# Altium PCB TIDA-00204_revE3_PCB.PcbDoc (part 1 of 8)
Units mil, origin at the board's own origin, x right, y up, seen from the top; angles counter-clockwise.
Board outline 4600 x 3740 mil, 8 copper layers (TopLayer - S1 (.GTL), MidLayer1 - S2 (.G1), MidLayer2 - S3 (.G2), MidLayer3 - S4 (.G3), MidLayer4 - S5 (.G4), MidLayer5 - S6 (.G5), MidLayer6 - S7 (.G6), BottomLayer - S8 (.GBL)), stack 58.938 mil thick; 536 components, 354 nets, 2015 pads, 1067 vias.
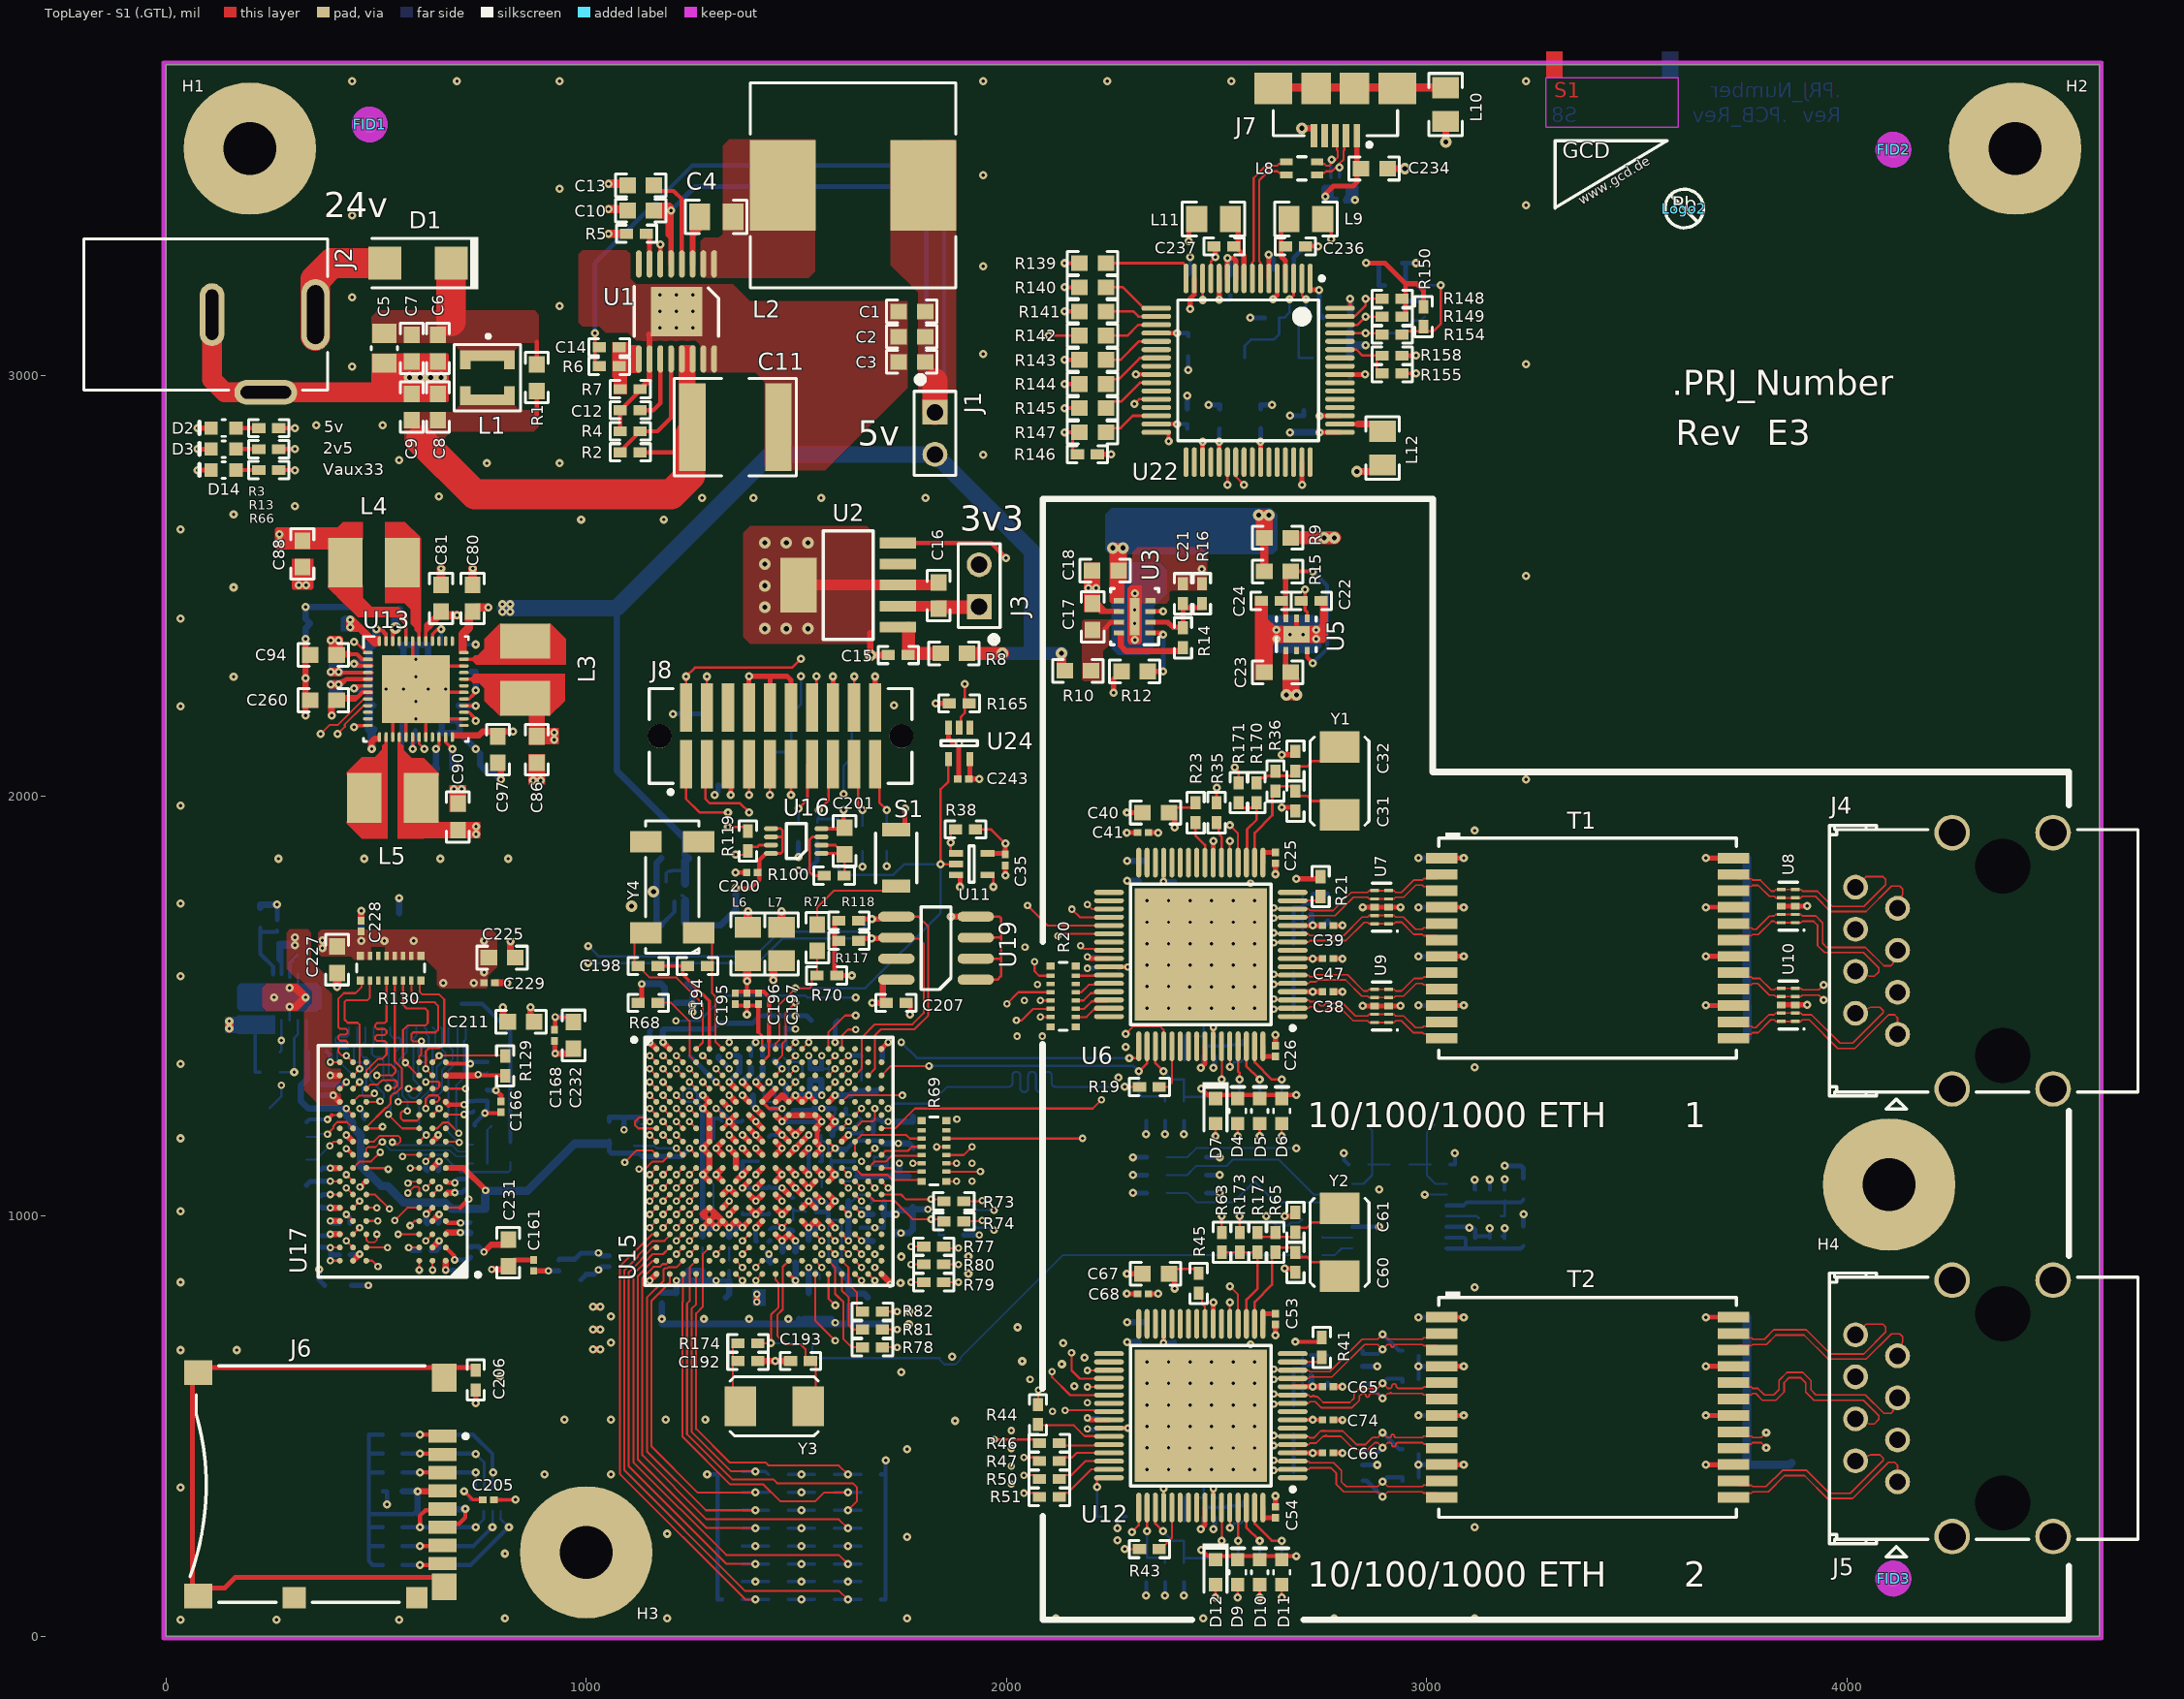
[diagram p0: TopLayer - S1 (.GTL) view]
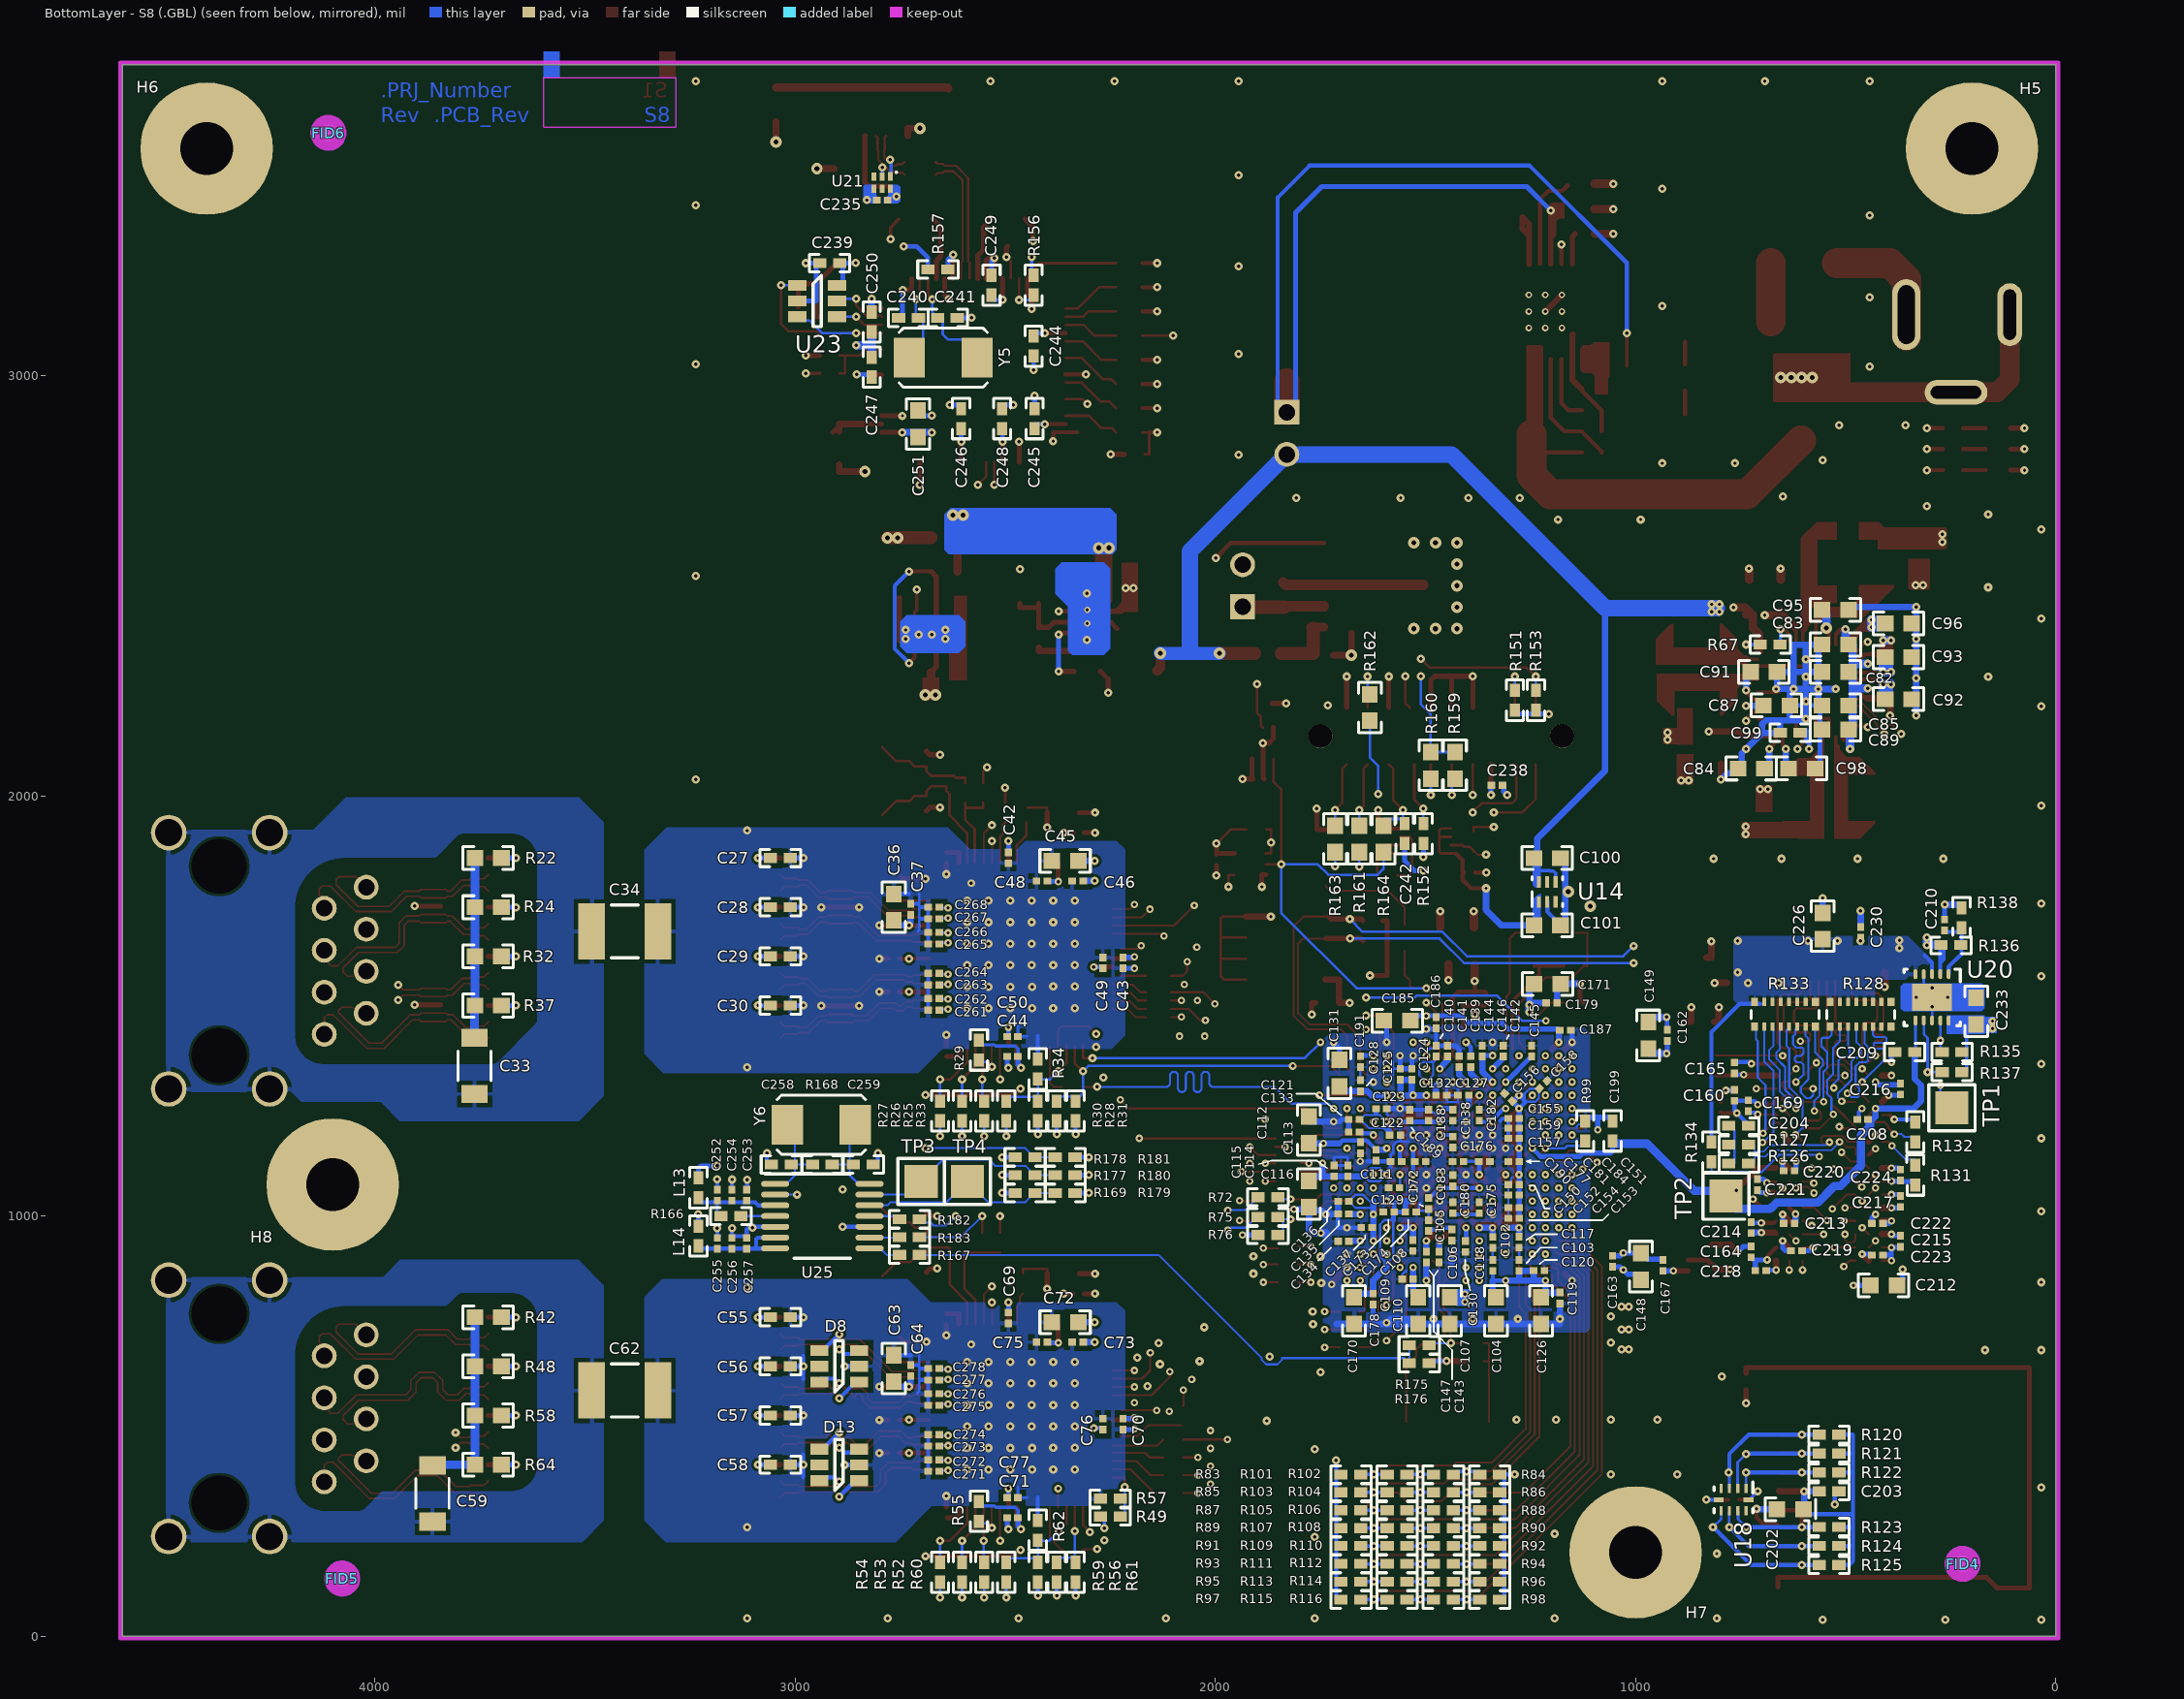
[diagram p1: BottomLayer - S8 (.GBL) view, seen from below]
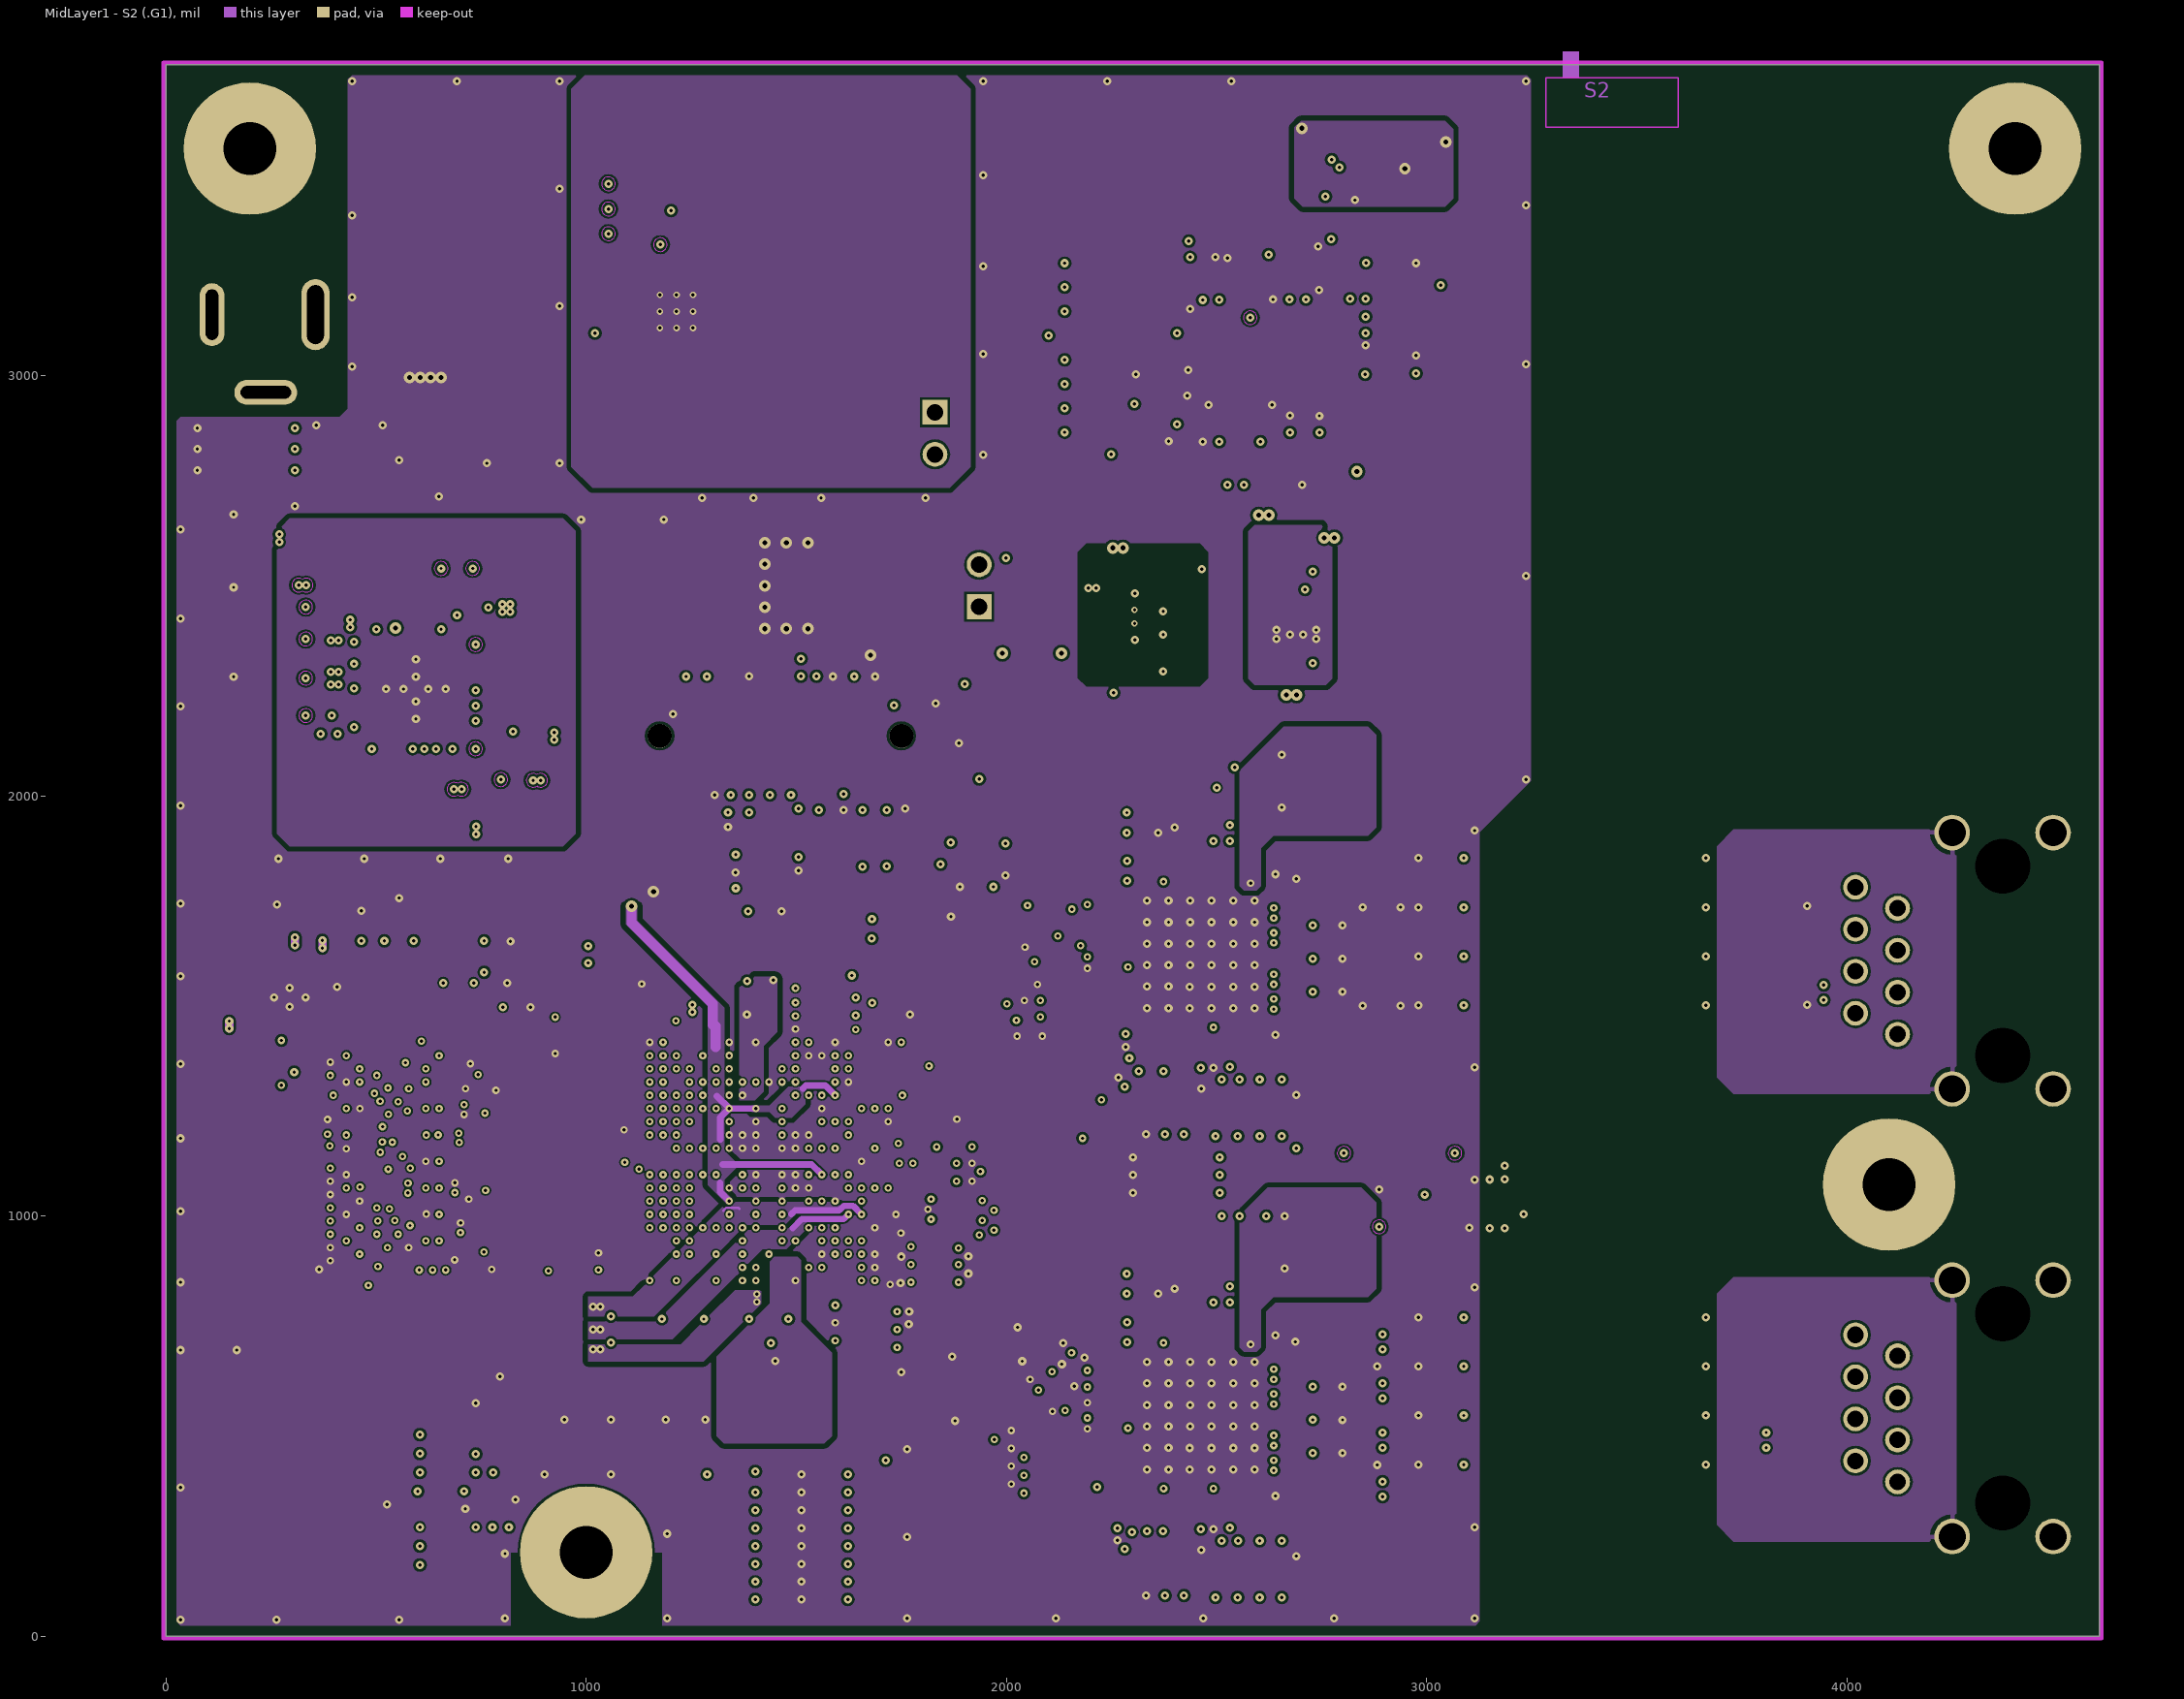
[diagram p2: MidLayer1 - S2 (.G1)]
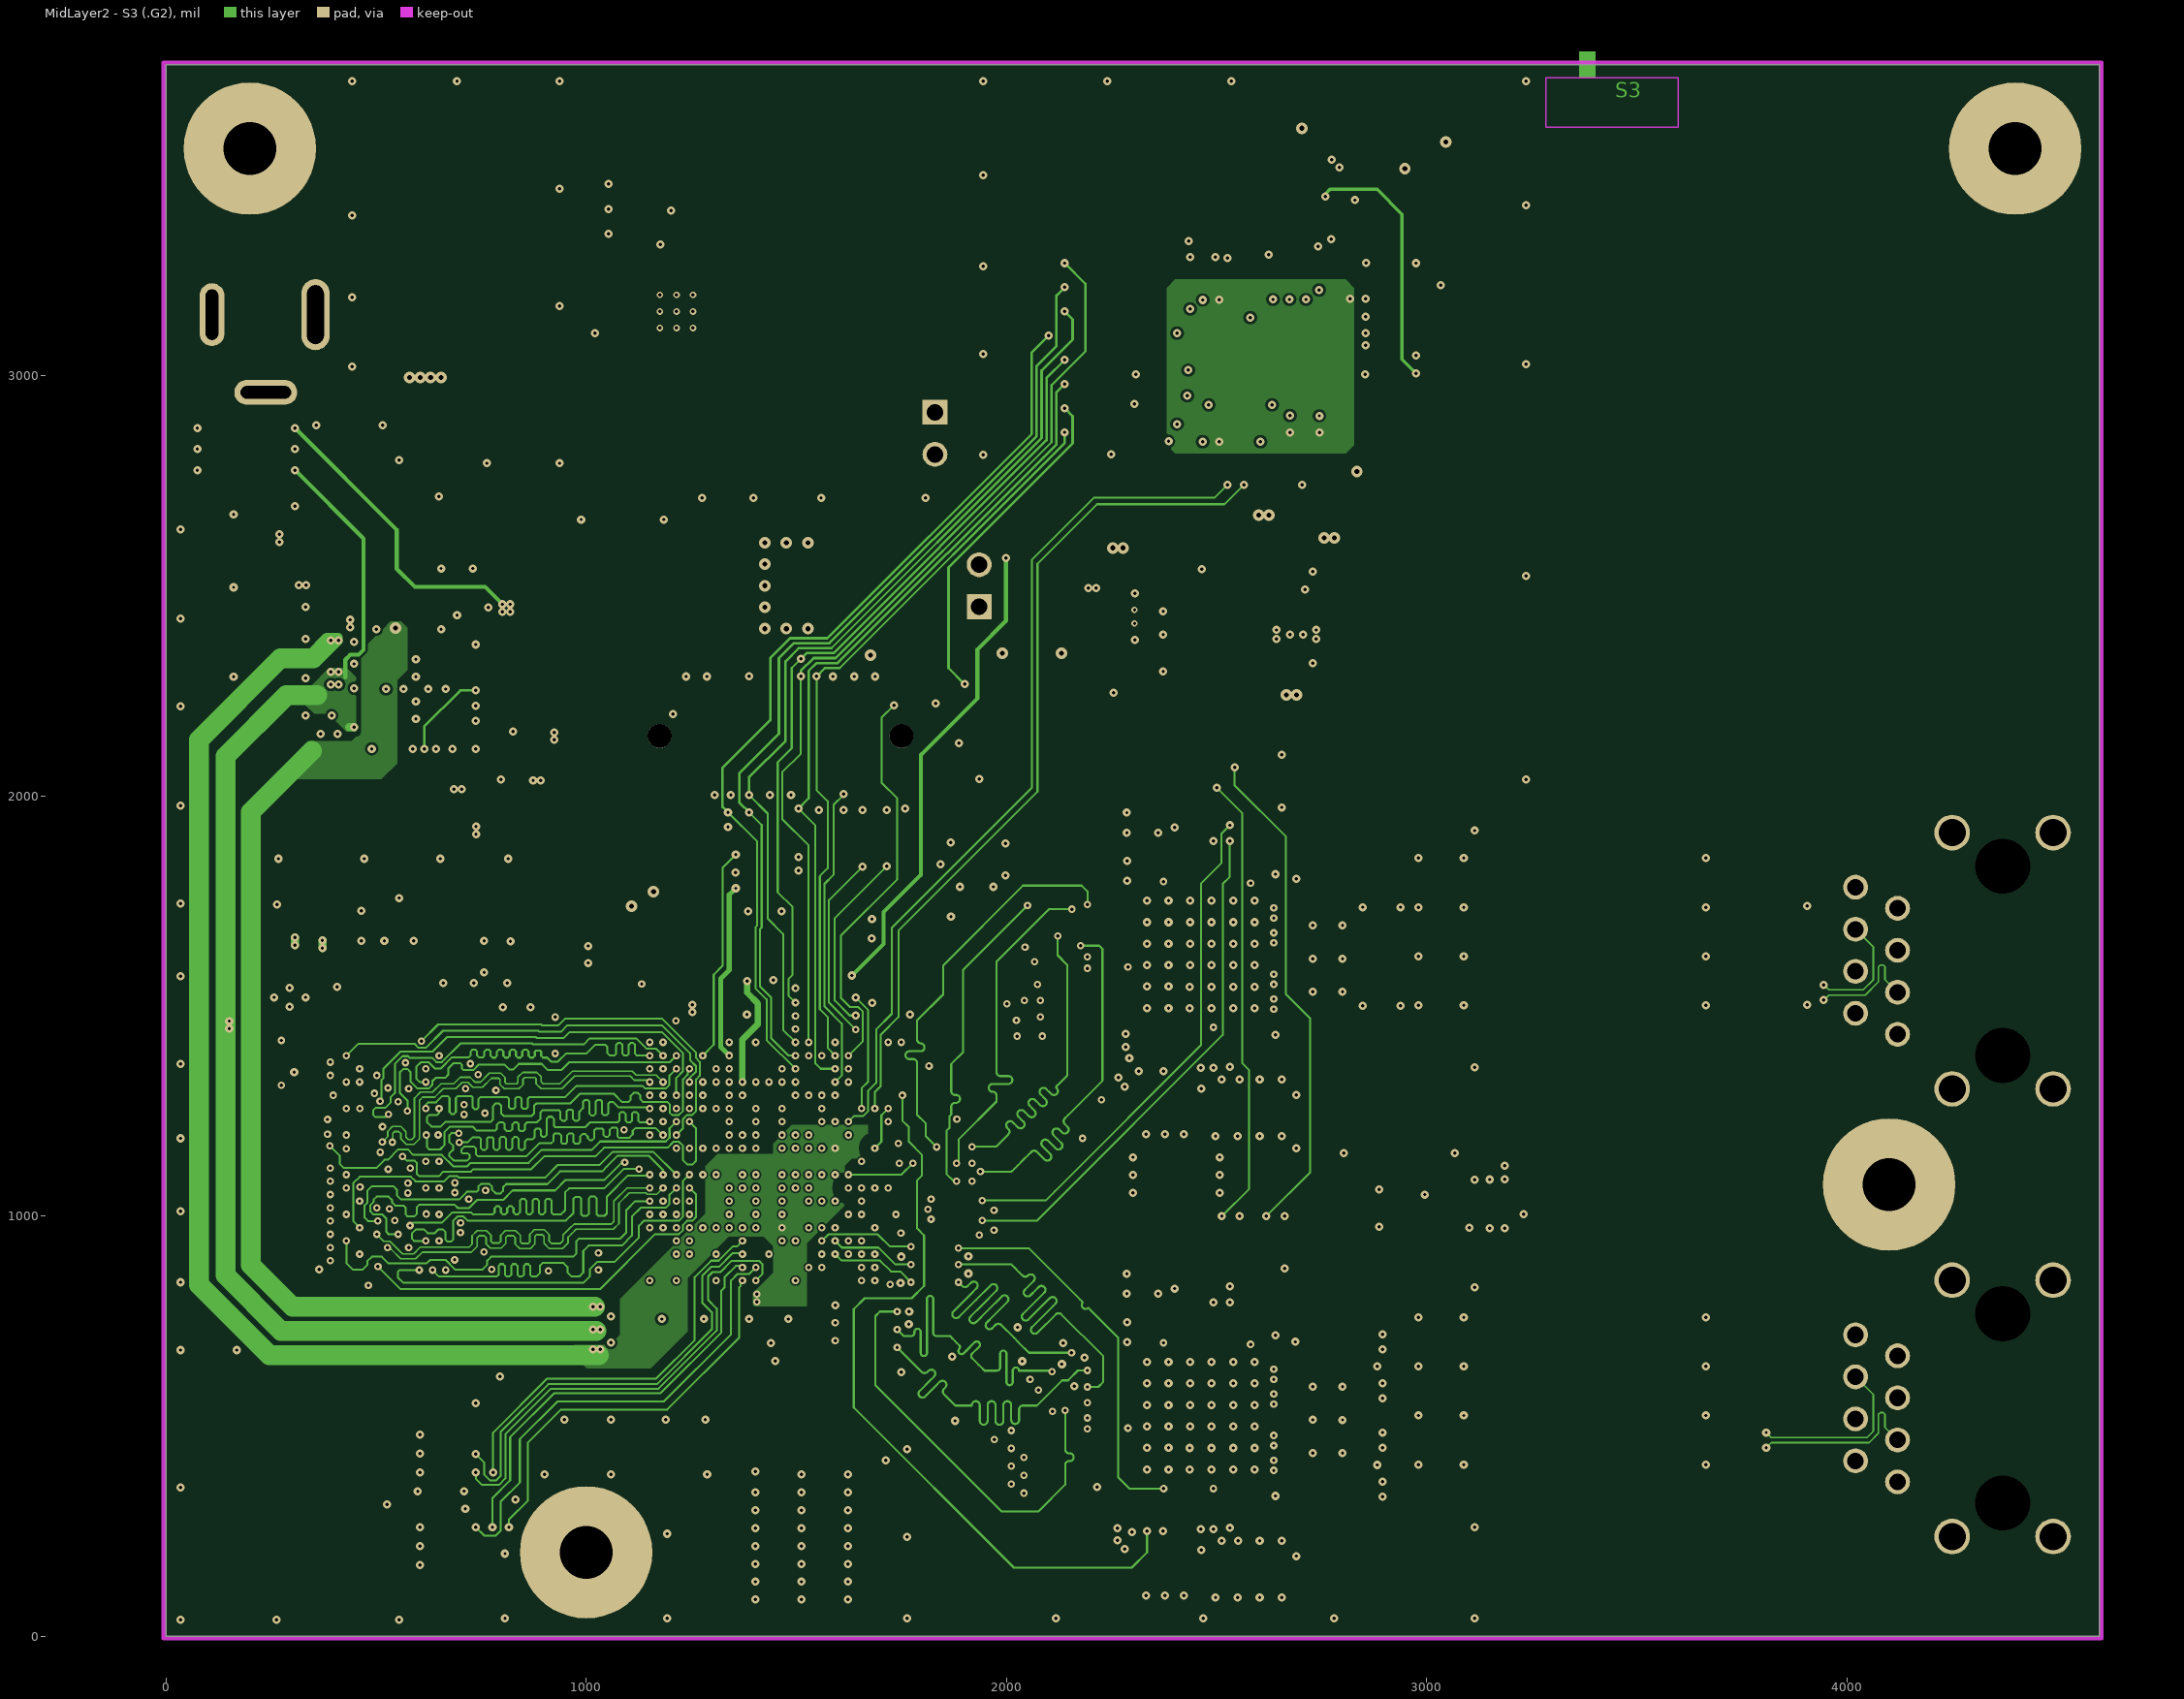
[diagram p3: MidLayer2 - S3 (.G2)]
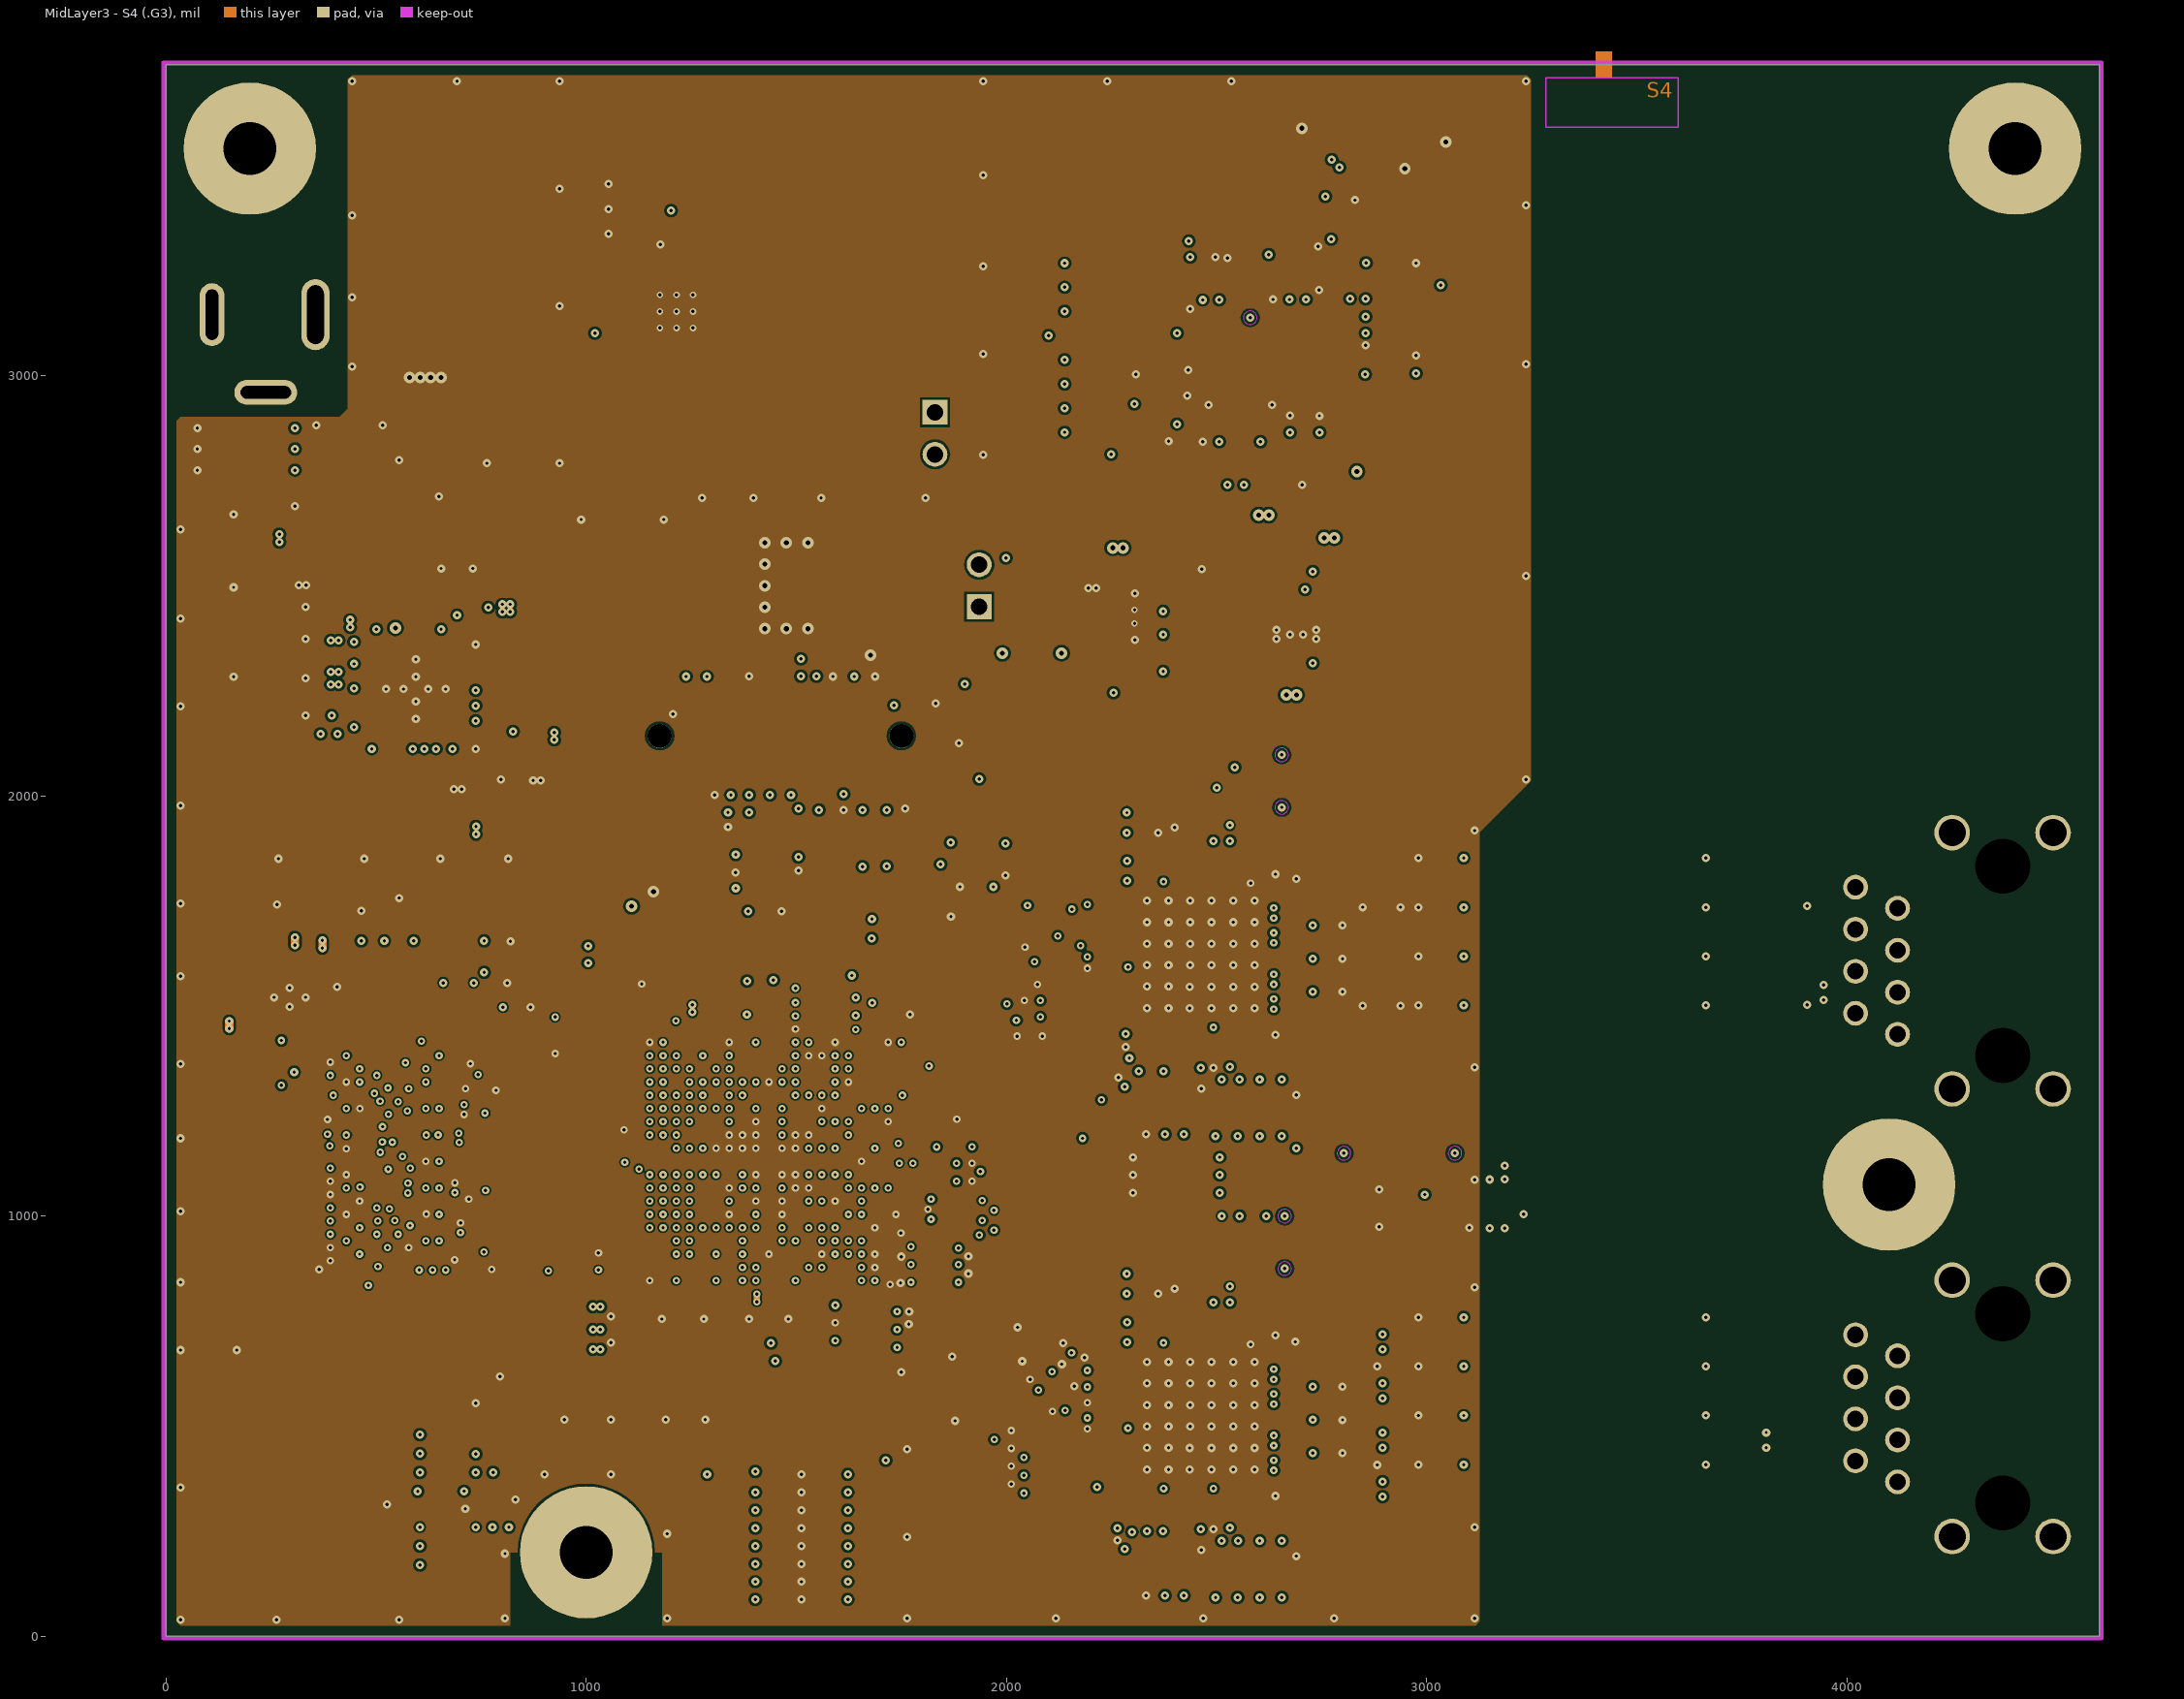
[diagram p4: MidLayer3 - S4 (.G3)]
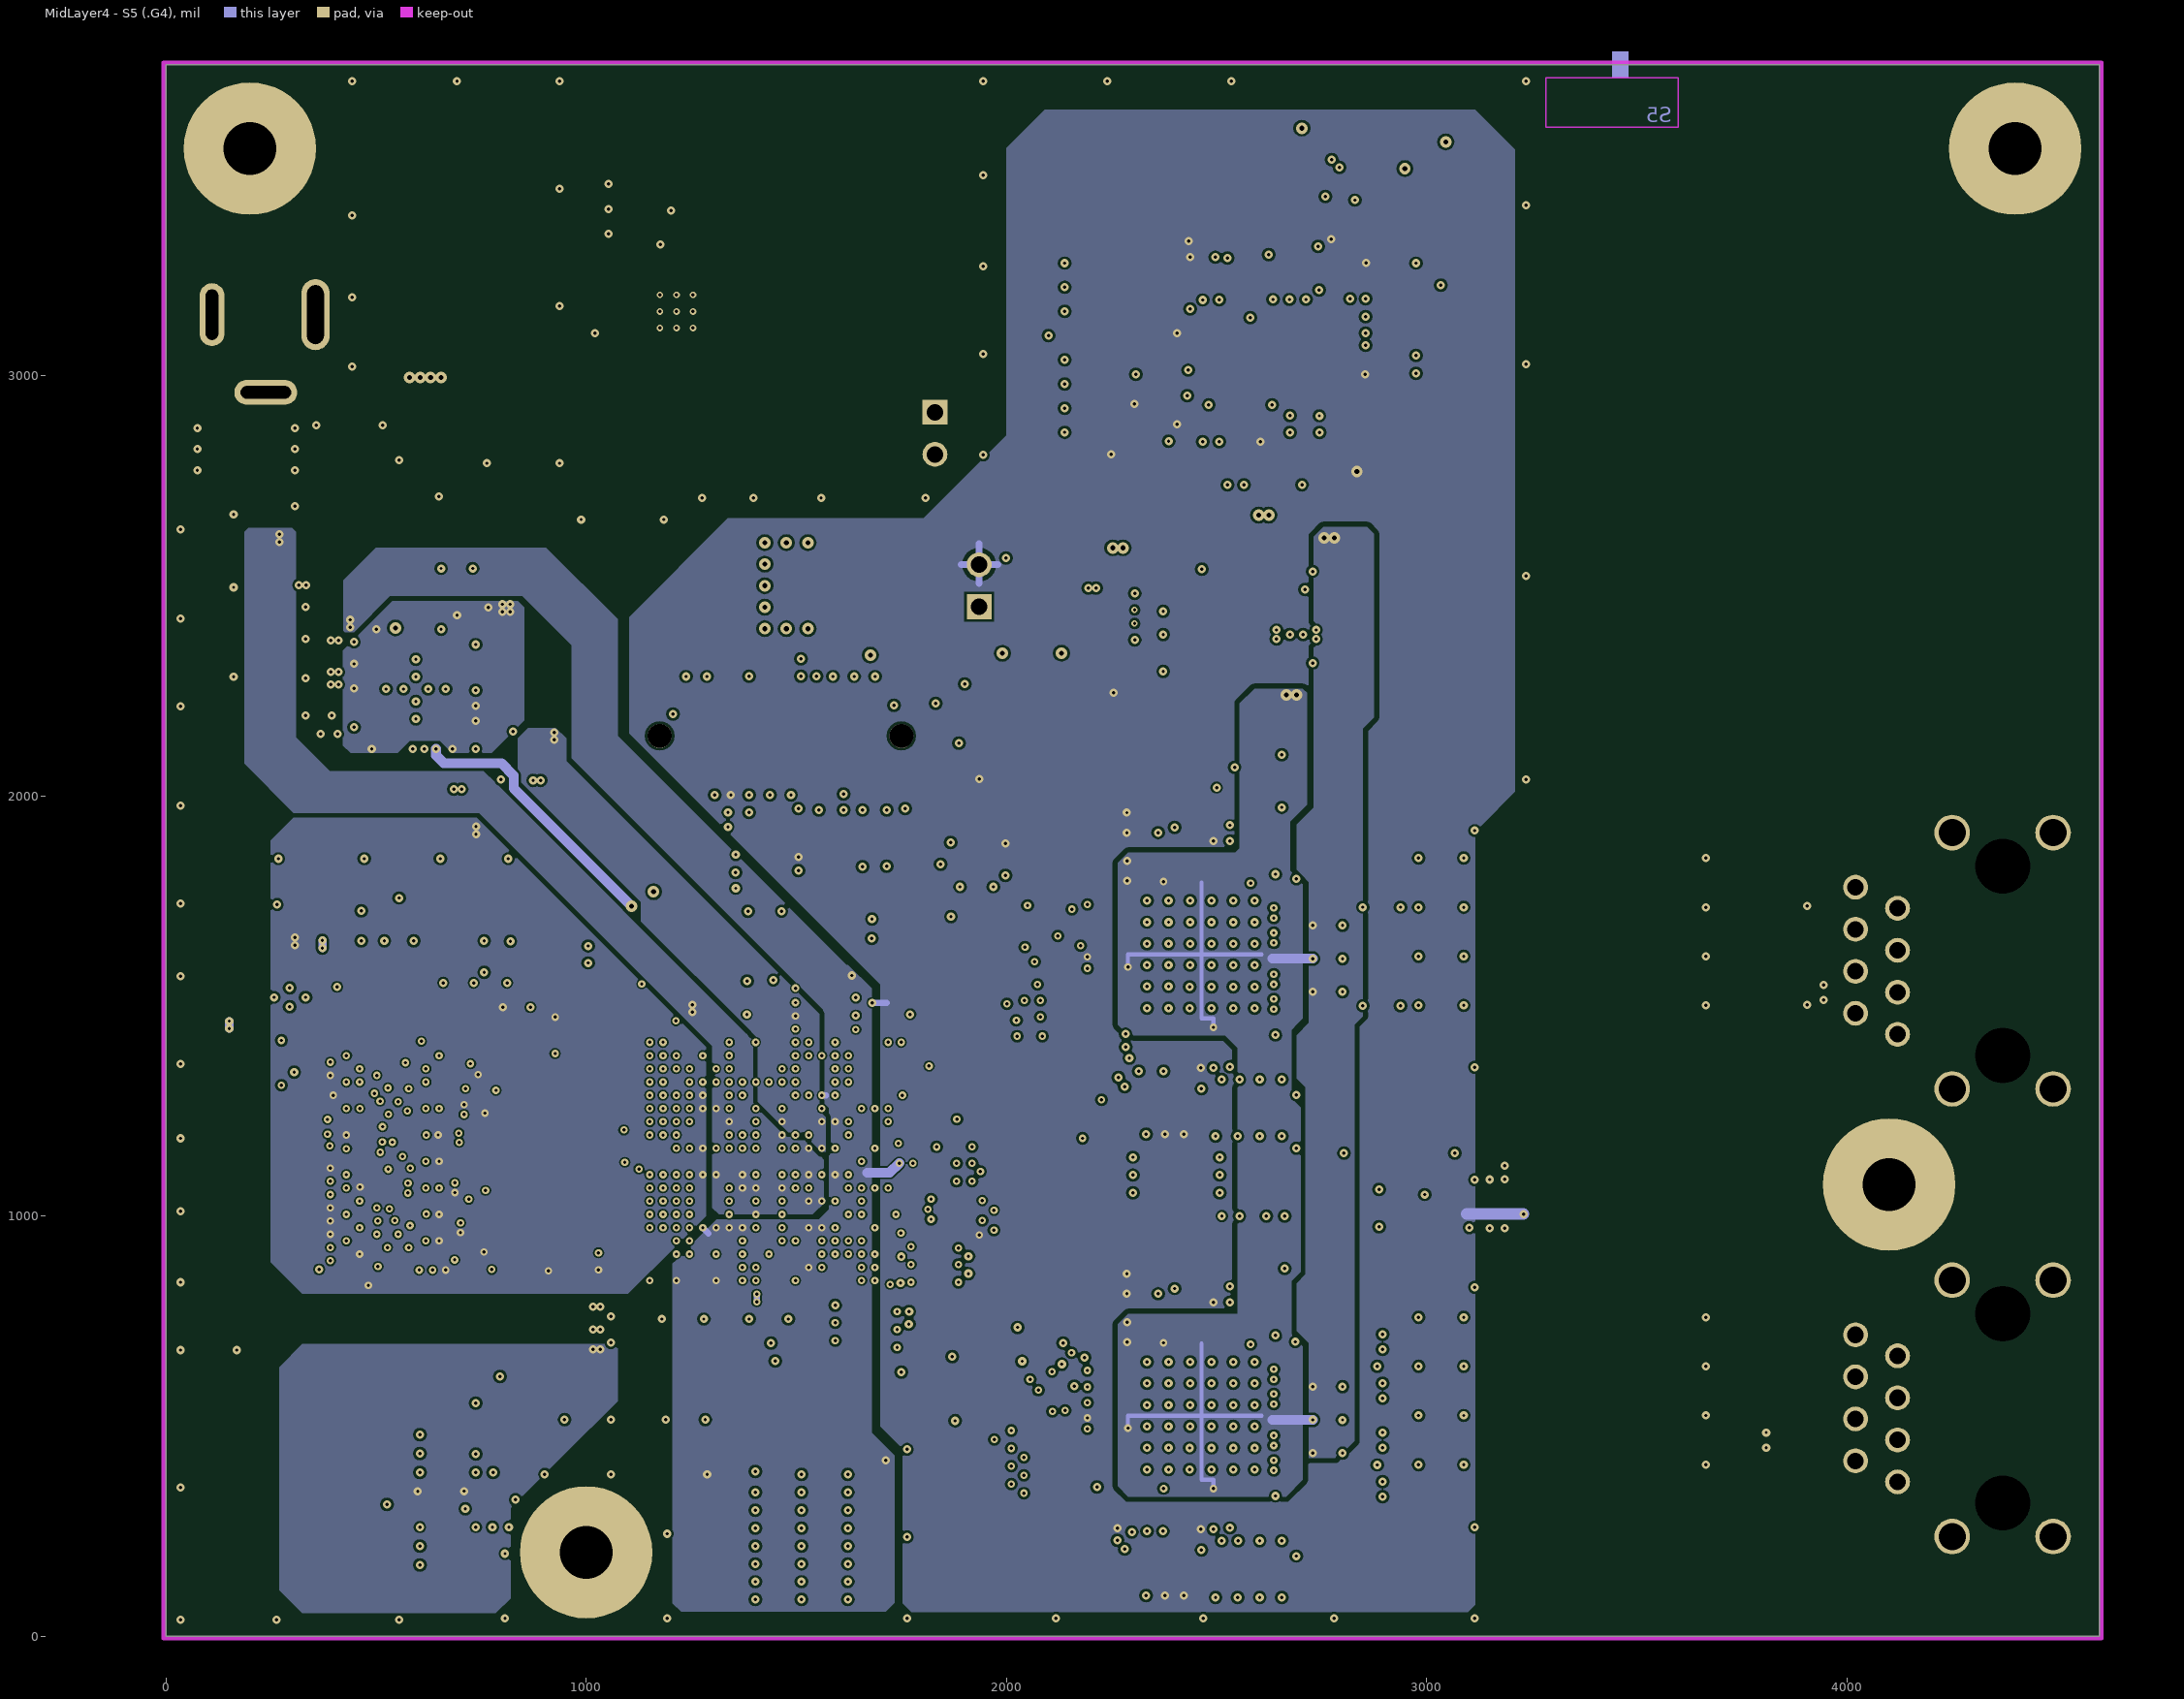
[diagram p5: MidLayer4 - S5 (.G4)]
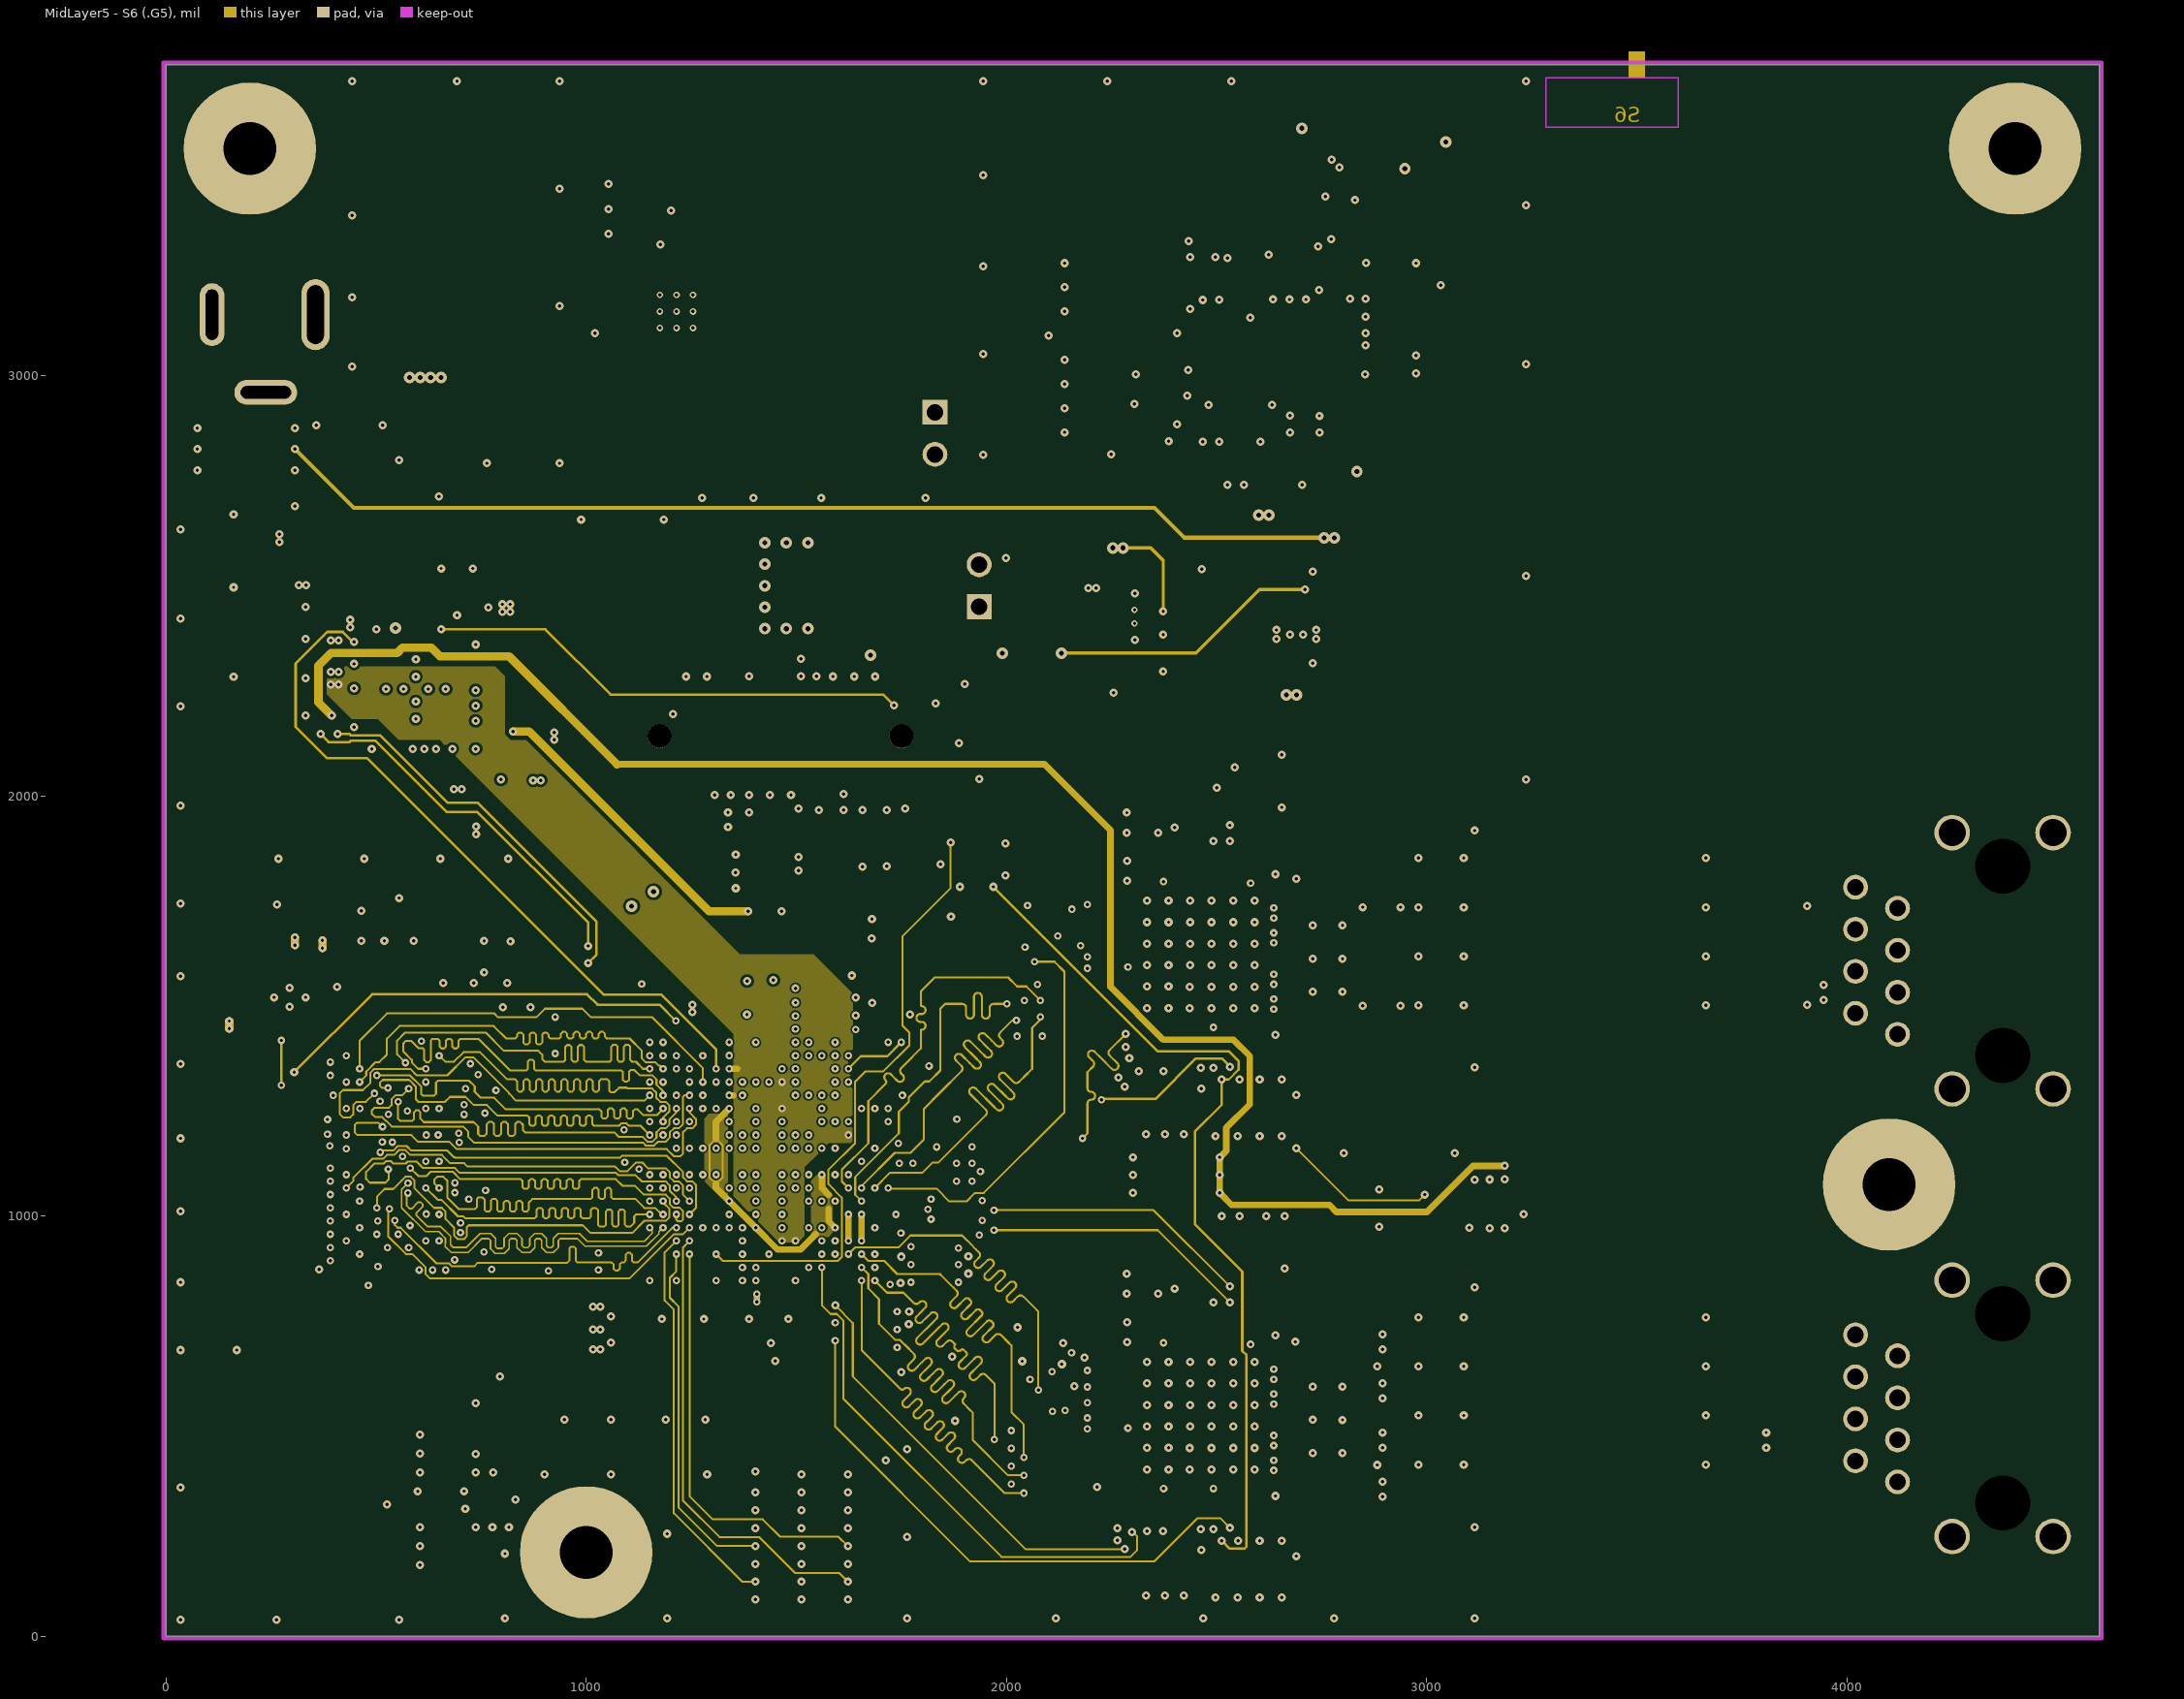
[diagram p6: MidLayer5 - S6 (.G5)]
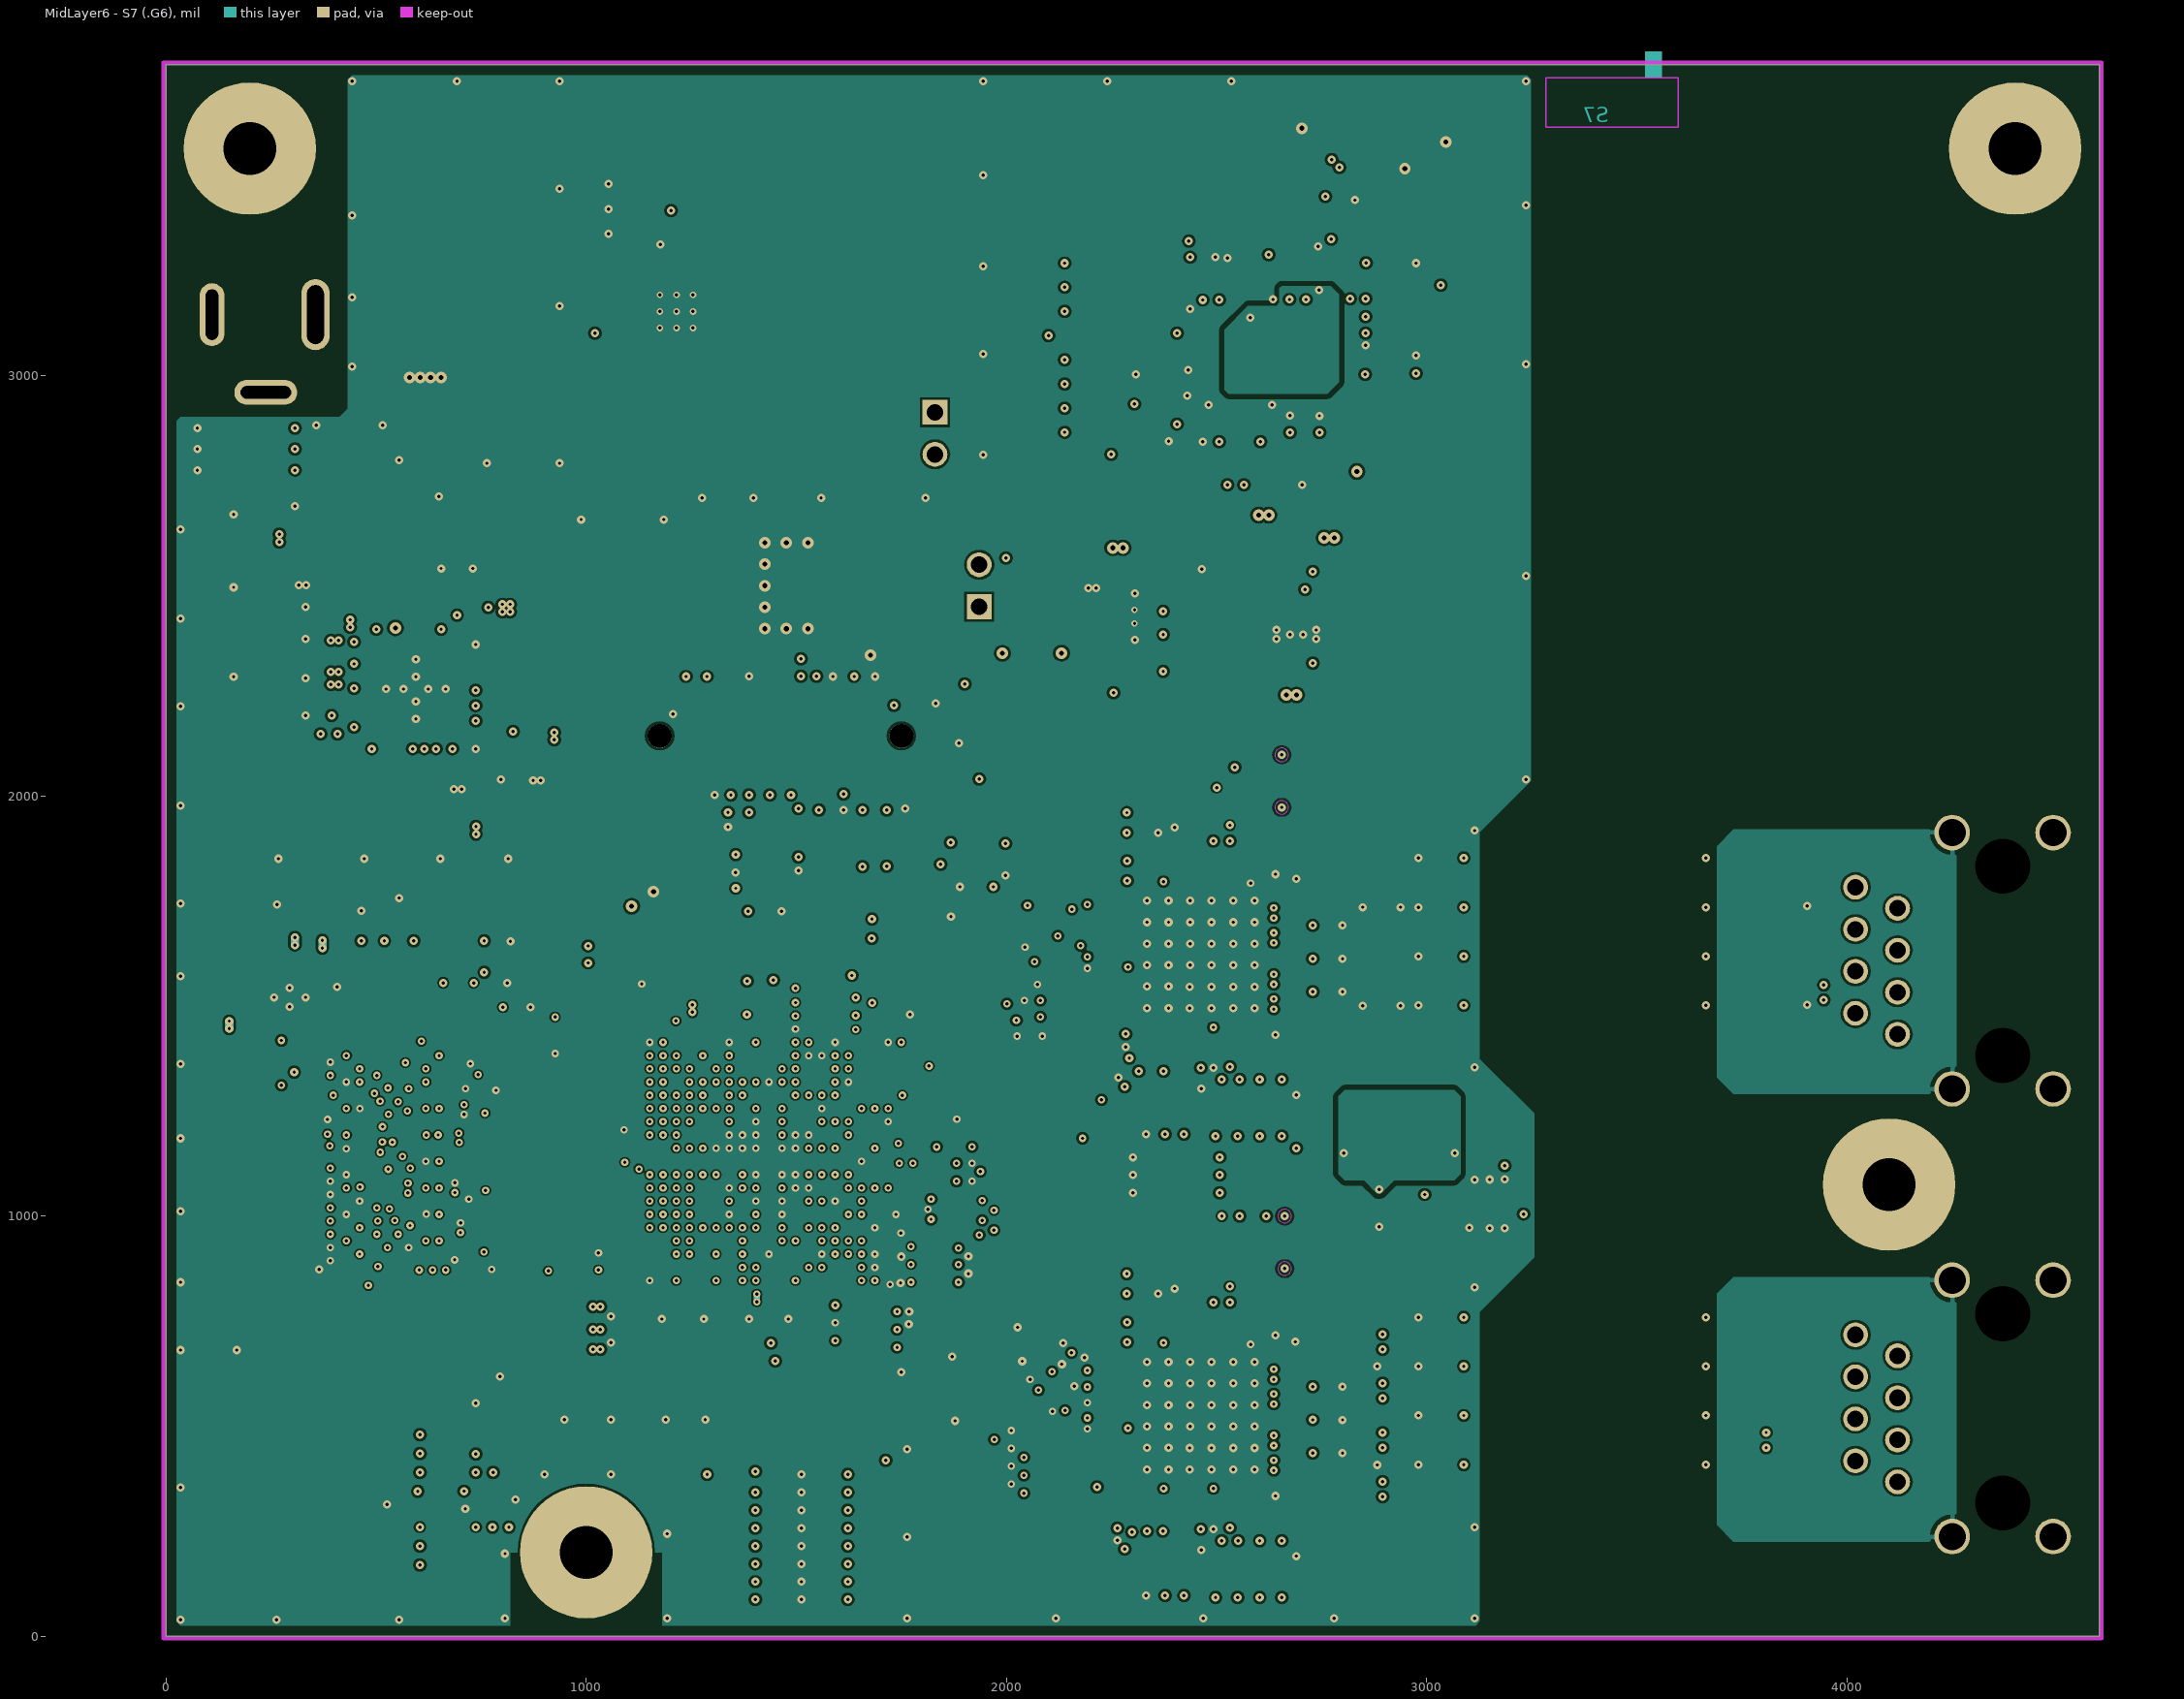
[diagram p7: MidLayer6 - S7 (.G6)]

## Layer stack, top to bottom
Top Solder: solder mask 0.591, Solder Resist, Dk 3.9
TopLayer - S1 (.GTL): signal copper 0.709
Dielectric1: prepreg 3.346, FR4, IS420ML, 1x 1080 (Prepreg), Dk 4.36
MidLayer1 - S2 (.G1): signal copper 0.709
Dielectric2: core 3.976, FR4, IS420ML, 1x 2116 (Core), Dk 4.72
MidLayer2 - S3 (.G2): signal copper 0.709
Dielectric3: prepreg 17.323, FR4, IS420ML, 3x 2157 (Prepreg), Dk 4.75
MidLayer3 - S4 (.G3): signal copper 0.709
Dielectric4: core 3.976, FR4, IS420ML, 1x 2116 (Core), Dk 4.72
MidLayer4 - S5 (.G4): signal copper 0.709
Dielectric5: prepreg 17.323, FR4, IS420ML, 3x 2157 (Prepreg), Dk 4.75
MidLayer5 - S6 (.G5): signal copper 0.709
Dielectric 6: core 3.976, FR4, IS420ML, 1x 2116 (Core), Dk 4.72
MidLayer6 - S7 (.G6): signal copper 0.709
Dielectric 7: prepreg 3.346, FR4, IS420ML, 1x 1080 (Prepreg), Dk 4.36
BottomLayer - S8 (.GBL): signal copper 0.709
Bottom Solder: solder mask 0.591, Solder Resist, Dk 3.9

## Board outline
0,0 0,3740 4600,3740 4600,0

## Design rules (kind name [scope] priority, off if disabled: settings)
AcuteAngle [All] p1: minimum=4.50000000000000E+0001 checktracksonly=FALSE
AssemblyTestPointUsage [All] p1: valid=2
Clearance Clearance_PHY2_CLK [InNetClass('PHY2_CLK') vs Not(InRegion(2300,2200,2500,2500)) and (((InNetClass('RGMII2_RX')) or (InNetClass('RGMII2_TX'))) and (Layer = 'MidLayer5 - S6 (.G5)') or (Layer = 'MidLayer2 - S3 (.G2)'))] p1: gap=50 except(5: Arc-Via Track-Via)
Clearance Clearance_PHY1_CLK [InNetClass('PHY1_CLK') vs Not(InRegion(2300,2550,2700,2850))  and (((InNetClass('RGMII1_RX')) or (InNetClass('RGMII1_TX'))) and (Layer = 'MidLayer5 - S6 (.G5)') or (Layer = 'MidLayer2 - S3 (.G2)'))] p2: gap=50 except(5: Arc-Via Track-Via)
Clearance Clearance_PHY2_Data_RX [InNetClass('RGMII2_RX') vs Not(InRegion(2300,2200,2500,2500)) and (((InNetClass('RGMII2_RX')) or (InNetClass('RGMII2_TX'))) and (Layer = 'MidLayer5 - S6 (.G5)') or (Layer = 'MidLayer2 - S3 (.G2)'))] p3: gap=30 except(5: Arc-Via Track-Via)
Clearance Clearance_PHY1_Data_RX [InNetClass('RGMII1_RX') vs Not(InRegion(2300,2550,2700,2850)) and (((InNetClass('RGMII1_RX')) or (InNetClass('RGMII1_TX'))) and (Layer = 'MidLayer5 - S6 (.G5)') or (Layer = 'MidLayer2 - S3 (.G2)'))] p4: gap=30 except(5: Arc-Via Track-Via)
Clearance Clearance_PHY2_Data_TX [InNetClass('RGMII2_TX') vs Not(InRegion(2300,2200,2500,2500)) and (((InNetClass('RGMII2_RX')) or (InNetClass('RGMII2_TX'))) and (Layer = 'MidLayer5 - S6 (.G5)') or (Layer = 'MidLayer2 - S3 (.G2)'))] p5: gap=30 except(5: Arc-Via Track-Via)
Clearance Clearance_PHY1Data_TX [InNetClass('RGMII1_TX') vs Not(InRegion(2300,2550,2700,2850)) and (((InNetClass('RGMII2_RX')) or (InNetClass('RGMII2_TX'))) and (Layer = 'MidLayer5 - S6 (.G5)') or (Layer = 'MidLayer2 - S3 (.G2)'))] p6: gap=30 except(5: Arc-Via Track-Via)
Clearance Clearance_BoardEdge_MountingHoles [OnCopper and InComponentClass('Mounting Holes') vs IsKeepOut  and not ((ObjectKind = 'Arc') And (AsMils(Width) = 0.5) And (Keepout = 'True'))] p7: gap=40
Clearance Clearance_All-to-MountingHoles [(ObjectKind = 'Pad') And (Layer = 'MultiLayer') And (AsMM(HoleDiameter) = 3.2) And (AsMM(PadXSize_AllLayers) = 8) And (AsMM(PadYSize_AllLayers) = 8)] p8: gap=23.62
Clearance Clearance_Keepouts [((IsTrack Or IsArc) And Not InPoly) And IsFree and IsKeepOut vs ((IsTrack Or IsArc) And Not InPoly) And IsFree and IsKeepOut] p9: gap=0
Clearance Clearance_BoardEdge_Poly [OnCopper and InPoly vs IsKeepOut  and not ((ObjectKind = 'Arc') And (AsMils(Width) = 0.5) And (Keepout = 'True'))] p10: gap=25
Clearance Clearance_BoardEdge [OnCopper and Not InComponentClass('Logo') and not InComponentClass('FiducialMark') and not InRegion(1000,500,4000,800) and Not IsKeepout vs IsKeepOut  and not ((ObjectKind = 'Arc') And (AsMils(Width) = 0.5) And (Keepout = 'True'))] p11: gap=19.6
Clearance Clearance_CLKs [InNetClass('CLKs') vs All and not (WithinRoom('RuleArea_BGA 0.8mm') or IsVia or IsSMTPin)] p12: gap=14.76 except(4.33: Via-Poly; 5.91: Track-SMDPad Track-Via SMDPad-SMDPad)
Clearance Clearance_PWR [InNetClass('PWR') and not OnTop vs InNetClass('PWR')] p13 off: gap=9.84 except(5.91: Via-Poly Poly-Poly)
Clearance Clearance_Poly-to-Poly [InPolygon vs InPolygon] p14: gap=12
Clearance "Clearance_BGA 0.8mm_BottomLayer&Poly" [WithinRoom('RuleArea_BGA 0.8mm') and OnBottomLayer] p15: gap=3.94 except(4.92: Track-Poly SMDPad-Poly)
Clearance "Clearance_BGA 0.8mm" [WithinRoom('RuleArea_BGA 0.8mm')] p16: gap=3.94
Clearance [All] p17: gap=5.91 except(11.81: SMDPad-Poly Poly-Poly)
Clearance Clearance_Poly [InPolygon vs All and not (OnBottomLayer or OnTopLayer)] p18 off: gap=25
ComponentClearance ComponentClearance_MountingHoles_FiducialMarks [InComponentClass('Mounting Holes') vs InComponentClass('FiducialMark')] p1 off: gap=50 collisioncheckmode=3 verticalgap=10 showdistances=FALSE
ComponentClearance ComponentClearance_Shunt [InComponentClass('Header') vs InComponentClass('Shunt')] p2 off: gap=0 collisioncheckmode=3 verticalgap=0 showdistances=FALSE
ComponentClearance ComponentClearance_Logo [InComponentClass('Logo')] p3 off: gap=50 collisioncheckmode=3 verticalgap=10 showdistances=FALSE
ComponentClearance ComponentClearance_ScrewToNut [(HasFootprint('NY PMS 440 0025 PH')) vs (HasFootprint('Keystone_1902C'))] p4 off: gap=5 collisioncheckmode=3 verticalgap=10 showdistances=FALSE
ComponentClearance ComponentClearance_MountingHoles [InComponentClass('Mounting Holes')] p5 off: gap=250 collisioncheckmode=3 verticalgap=100000 showdistances=FALSE
ComponentClearance ComponentClearance_SmallPassives [HasFootprint('0402*') or HasFootprint('0508') or HasFootprint('0603*') or HasFootprint('0612') or HasFootprint('0805*') or HasFootprint('0815*') or HasFootprint('0830*') or HasFootprint('1206*') or HasFootprint('1210*') or HasFootprint('1808*') or HasFootprint('1812*') or HasFootprint('1825*') or HasFootprint('2010*') or HasFootprint('2220*') or HasFootprint('2225*') or HasFootprint('2512*') or HasFootprint('2728*') or HasFootprint('3518*') vs HasFootprint('0402*') or HasFootprint('0508') or HasFootprint('0603*') or HasFootprint('0612') or HasFootprint('0805*') or HasFootprint('0815*') or HasFootprint('0830*') or HasFootprint('1206*') or HasFootprint('1210*') or HasFootprint('1808*') or HasFootprint('1812*') or HasFootprint('1825*') or HasFootprint('2010*') or HasFootprint('2220*') or HasFootprint('2225*') or HasFootprint('2512*') or HasFootprint('2728*') or HasFootprint('3518*')] p6: gap=17.72 collisioncheckmode=3 verticalgap=10 showdistances=TRUE
ComponentClearance ComponentClearance_THtoSMT [IsThruComponent vs IsSMTComponent and OnBottom] p7 off: gap=100 collisioncheckmode=3 verticalgap=30 showdistances=FALSE
ComponentClearance ComponentClearance_THtoTH [IsThruComponent vs IsThruComponent] p8 off: gap=118.11 collisioncheckmode=3 verticalgap=30 showdistances=FALSE
ComponentClearance [All] p9 off: gap=10 collisioncheckmode=3 verticalgap=10 showdistances=FALSE
DiffPairsRouting DiffPairs_100R [InDifferentialPairClass('Zdiff=100R')] p1: maxlimit=10 minlimit=8.27 mostfreqgap=8.27 toplayer_mingap=8.46 toplayer_prefgap=8.46 toplayer_minwidth=3.98 toplayer_maxwidth=5.91 toplayer_prefwidth=3.98 midlayer1_minwidth=3.98 midlayer1_maxwidth=5.91 midlayer1_prefwidth=3.98 midlayer2_minwidth=3.98 midlayer2_maxwidth=5.91 midlayer2_prefwidth=3.98 midlayer3_minwidth=3.98 midlayer3_maxwidth=5.91 midlayer3_prefwidth=3.98 midlayer4_minwidth=3.98 midlayer4_maxwidth=5.91 midlayer4_prefwidth=3.98 midlayer5_minwidth=3.98 midlayer5_maxwidth=5.91 midlayer5_prefwidth=3.98 midlayer6_minwidth=3.98 midlayer6_maxwidth=5.91 midlayer6_prefwidth=3.98 bottomlayer_mingap=8.46 bottomlayer_prefgap=8.46 bottomlayer_minwidth=3.98 bottomlayer_maxwidth=11.81 bottomlayer_prefwidth=3.98 maxuncoupledlength=1259.84
DiffPairsRouting DiffPairs_90R [InDifferentialPairClass('Zdiff=90R')] p2: maxlimit=10 minlimit=8.27 mostfreqgap=8.27 toplayer_minwidth=5.12 toplayer_maxwidth=10 toplayer_prefwidth=5.12 midlayer1_minwidth=5.12 midlayer1_maxwidth=10 midlayer1_prefwidth=5.12 midlayer2_minwidth=5.12 midlayer2_maxwidth=10 midlayer2_prefwidth=5.12 midlayer3_minwidth=5.12 midlayer3_maxwidth=10 midlayer3_prefwidth=5.12 midlayer4_minwidth=5.12 midlayer4_maxwidth=10 midlayer4_prefwidth=5.12 midlayer5_minwidth=5.12 midlayer5_maxwidth=10 midlayer5_prefwidth=5.12 midlayer6_minwidth=5.12 midlayer6_maxwidth=10 midlayer6_prefwidth=5.12 bottomlayer_minwidth=5.12 bottomlayer_maxwidth=10 bottomlayer_prefwidth=5.12 maxuncoupledlength=200
DiffPairsRouting [All] p3 off: maxlimit=100 minlimit=10 mostfreqgap=10 toplayer_minwidth=3 toplayer_maxwidth=15 toplayer_prefwidth=15 midlayer1_minwidth=3 midlayer1_maxwidth=15 midlayer1_prefwidth=15 midlayer2_minwidth=3 midlayer2_maxwidth=15 midlayer2_prefwidth=15 midlayer3_minwidth=3 midlayer3_maxwidth=15 midlayer3_prefwidth=15 midlayer4_minwidth=3 midlayer4_maxwidth=15 midlayer4_prefwidth=15 midlayer5_minwidth=15 midlayer5_maxwidth=15 midlayer5_prefwidth=15 midlayer6_minwidth=15 midlayer6_maxwidth=15 midlayer6_prefwidth=15 bottomlayer_minwidth=3 bottomlayer_maxwidth=15 bottomlayer_prefwidth=15 maxuncoupledlength=1259.84
FabricationTestPointUsage TestPointUsage [All] p1: valid=2 allowmultiple=FALSE
FabricationTestpoint Testpoint [All] p1: side=3 testpointundercomponent=TRUE minsize=40 maxsize=100 preferedsize=60 minholesize=0 maxholesize=40 preferedholesize=32 testpointgrid=1 allowsidetop=TRUE allowsidebottom=TRUE usegrid=TRUE gridtolerance=0.01
FanoutControl Fanout_LCC [IsLCC] p1: bgadir=Out bgaviamode=Centered fanoutstyle=Auto fanoutdirection=Alternating viagrid=1 // Fanout_LCC (Default Rule)
FanoutControl Fanout_BGA [IsBGA] p2: bgadir=Out bgaviamode=Centered fanoutstyle=Auto fanoutdirection=Alternating viagrid=1 // Fanout_BGA (Default Rule)
FanoutControl Fanout_Default [All] p4: bgadir=Out bgaviamode=Centered fanoutstyle=Auto fanoutdirection=Alternating viagrid=1 // Fanout_Default (Default Rule)
FanoutControl Fanout_Small [(CompPinCount < 5)] p5: bgadir=Out bgaviamode=Centered fanoutstyle=Auto fanoutdirection=OutThenIn viagrid=1 // Fanout_Small (Default Rule)
Height [All] p1 off: minheight=0 maxheight=1000 prefheight=500
HoleSize [All] p1: absolutevalues=TRUE maxlimit=251 minlimit=7.5 maxpercent=80.000 minpercent=20.000
HoleToHoleClearance [All] p1: gap=9.84 allowstackedmicrovias=TRUE
MatchedLengths MatchLengths_xSignals_U12_U15_1 [InxSignalClass('xSignals_U12_U15_MatchLengthsClass')] p1: tolerance=10 checknetsindiffpair=FALSE checkdiffpairvsdiffpair=TRUE checkxsignals=TRUE checkothers=TRUE
MatchedLengths MatchLengths_xSignals_U6_U15_1 [InxSignalClass('xSignals_U6_U15_MatchLengthsClass')] p2: tolerance=10 checknetsindiffpair=FALSE checkdiffpairvsdiffpair=TRUE checkxsignals=TRUE checkothers=TRUE
MatchedLengths MatchLengths_xSignals_U12_U15 [InxSignalClass('xSignals_U12_U15_MatchLengthsClass')] p3: tolerance=10 checknetsindiffpair=FALSE checkdiffpairvsdiffpair=TRUE checkxsignals=TRUE checkothers=TRUE
MatchedLengths MatchLengths_xSignals_U6_U15 [InxSignalClass('xSignals_U6_U15_MatchLengthsClass_1')] p4: tolerance=10 checknetsindiffpair=FALSE checkdiffpairvsdiffpair=TRUE checkxsignals=TRUE checkothers=TRUE
MatchedLengths MatchedLengths_PHY2_X [InNetClass('PHY1_X')] p5: tolerance=39.37 checknetsindiffpair=TRUE checkdiffpairvsdiffpair=FALSE checkxsignals=FALSE checkothers=FALSE
MatchedLengths MatchedLengths_RGMII1_RX [InNetClass('RGMII1_RX')] p6 off: tolerance=39.37 checknetsindiffpair=TRUE checkdiffpairvsdiffpair=FALSE checkxsignals=FALSE checkothers=FALSE
MatchedLengths MatchedLengths_RGMII2_RX [InNetClass('RGMII2_RX')] p7 off: tolerance=10 checknetsindiffpair=TRUE checkdiffpairvsdiffpair=FALSE checkxsignals=FALSE checkothers=FALSE
MatchedLengths MatchedLengths_RGMII1_TX [InNetClass('RGMII1_TX')] p8 off: tolerance=39.37 checknetsindiffpair=TRUE checkdiffpairvsdiffpair=FALSE checkxsignals=FALSE checkothers=FALSE
MatchedLengths MatchedLengths_RGMII2_TX [InNetClass('RGMII2_TX')] p9 off: tolerance=10 checknetsindiffpair=TRUE checkdiffpairvsdiffpair=FALSE checkxsignals=FALSE checkothers=FALSE
MatchedLengths MatchedLengths_RGMII1_TX_R [InNetClass('RGMII1_TX_R')] p10 off: tolerance=39.37 checknetsindiffpair=TRUE checkdiffpairvsdiffpair=FALSE checkxsignals=FALSE checkothers=FALSE
MatchedLengths MatchedLengths_RGMII2_TX_R [InNetClass('RGMII2_TX_R')] p11 off: tolerance=10 checknetsindiffpair=TRUE checkdiffpairvsdiffpair=FALSE checkxsignals=FALSE checkothers=FALSE
MatchedLengths MatchedLengths_RGMII1_RX_R [InNetClass('RGMII1_RX_R')] p12 off: tolerance=39.37 checknetsindiffpair=TRUE checkdiffpairvsdiffpair=FALSE checkxsignals=FALSE checkothers=FALSE
MatchedLengths MatchedLengths_RGMII2_RX_R [InNetClass('RGMII2_RX_R')] p13 off: tolerance=10 checknetsindiffpair=TRUE checkdiffpairvsdiffpair=FALSE checkxsignals=FALSE checkothers=FALSE
MatchedLengths MatchedLengths_PHY1_X [InNetClass('PHY2_X')] p14: tolerance=39.37 checknetsindiffpair=TRUE checkdiffpairvsdiffpair=FALSE checkxsignals=FALSE checkothers=FALSE
MatchedLengths MatchedLengths_PHY1_TD [InNetClass('PHY1_TD')] p15: tolerance=39.37 checknetsindiffpair=TRUE checkdiffpairvsdiffpair=FALSE checkxsignals=FALSE checkothers=FALSE
MatchedLengths MatchedLengths_PHY2_TD [InNetClass('PHY2_TD')] p16: tolerance=10 checknetsindiffpair=TRUE checkdiffpairvsdiffpair=FALSE checkxsignals=FALSE checkothers=FALSE
MinimumAnnularRing MinimumAnnularRing_ThermalPadVias [IsVia and InAnyComponent] p1: minimumring=3.35
MinimumAnnularRing [All] p2: minimumring=4.88
MinimumSolderMaskSliver MinimumSolderMaskSliver_Logo [InComponentClass('Logo') vs InComponentClass('Logo')] p1: minsoldermaskwidth=0.7
MinimumSolderMaskSliver [All] p2: minsoldermaskwidth=2.72
ParallelSegment ParallelSegment_1 [InNetClass('PHY2_CLK') vs InNetClass('PHY2_TD')] p1: limit=5 gap=50
ParallelSegment [InNetClass('CLKs')] p2: limit=10000 gap=14.76
PlaneConnect [All] p1: planeconnectstyle=Relief reliefexpansion=10 reliefentries=4 reliefconductorwidth=10 reliefairgap=10
PolygonConnect PolygonConnect_Vias [IsVia] p1: connectstyle=Direct reliefconductorwidth=10 reliefentries=4 polygonreliefangle="90 Angle" airgapwidth=10
PolygonConnect "PolygonConnect_under BGA" [OnBottomLayer and WithinRoom('RuleArea_BGA 0.8mm')] p2: connectstyle=Relief reliefconductorwidth=5.91 reliefentries=4 polygonreliefangle="90 Angle" airgapwidth=4.92
PolygonConnect "PolygonConnect_DirectConnect on Top or Bottom" [OnTopLayer vs IsSMTPin] p3: connectstyle=Direct reliefconductorwidth=10 reliefentries=4 polygonreliefangle="90 Angle" airgapwidth=10
PolygonConnect [All] p4: connectstyle=Relief reliefconductorwidth=10 reliefentries=4 polygonreliefangle="90 Angle" airgapwidth=10
RoomDefinition TIDA-00204_revE3_PS_2 [InComponentClass('TIDA-00204_revE3_PS_2')] p1 off: confinementstyle=ConfineIn formatcopy=TRUE lockcomponents=FALSE outline 345,793.31 345,1557.09 1820.5,1557.09 1820.5,793.31
RoutingVias ThermalPadVias [IsVia and InAnyComponent] p1: holewidth=7.87 width=19.68 viastyle="Through Hole" minholewidth=7.87 minwidth=15 maxholewidth=12.99 maxwidth=23.62
RoutingVias [All] p2: holewidth=7.87 width=19.68 viastyle="Through Hole" minholewidth=7.87 minwidth=17.72 maxholewidth=39.37 maxwidth=62.99
SilkToBoardRegionClearance [Not ((IsComment or IsDesignator) And (Hide <> 'False')) and not InRegion(1000,500,4000,800)] p1:
SilkToSilkClearance SilkToSilkClearance_Pb-FreeLogo [(HasFootprint('Pb-Free_Overlay_Medium') OR HasFootprint('Pb-Free_Overlay_Small')) vs (HasFootprint('Pb-Free_Overlay_Medium') OR HasFootprint('Pb-Free_Overlay_Small'))] p1: silktosilkclearance=0
SilkToSilkClearance [All] p2: silktosilkclearance=3.94
SilkToSolderMaskClearance "Silk to Solder Mask Opening" [ALL and not isvia vs All and not isvia] p1: minsilkscreentomaskgap=0.98 clearancetoexposedcopper=FALSE
SolderMaskExpansion "SolderMaskExpansion_Vias (0.45/0.2)" [(ObjectKind = 'Via') And (ViaDiameter = AsMM(0.45)) And (HoleDiameter = AsMM(0.2))] p1: expansion=-4.33
SolderMaskExpansion "SolderMaskExpansion_Vias (0.5/0.2)" [(ObjectKind = 'Via') And (ViaDiameter = AsMM(0.5)) And (HoleDiameter = AsMM(0.2))] p2: expansion=-4.92
SolderMaskExpansion "SolderMaskExpansion_Vias (0.7/0.3)" [(ObjectKind = 'Via') And (ViaDiameter = AsMM(0.7)) And (HoleDiameter = AsMM(0.3))] p3: expansion=-7.28
SolderMaskExpansion "SolderMaskExpansion_Vias (28/10)" [(ObjectKind = 'Via') And (ViaDiameter = AsMils(28)) And (HoleDiameter = AsMils(10))] p4: expansion=-7
SolderMaskExpansion [All] p5: expansion=1.97
Width Width_Zdiff=100R [InNetClass('Zdiff=100R')] p1 off: maxlimit=11.81 minlimit=3.98 preferedwidth=3.98 toplayer_maxwidth=5.91 midlayer1_maxwidth=5.91 midlayer2_maxwidth=5.91 midlayer3_maxwidth=5.91 midlayer4_maxwidth=5.91 midlayer5_maxwidth=5.91 midlayer6_maxwidth=5.91 minimp=50.000000 maximp=50.000000 favimp=50.000000
Width Width_Zdiff=90R [InNetClass('Zdiff=90R')] p2 off: maxlimit=5.91 minlimit=5.12 preferedwidth=5.12 minimp=50.000000 maximp=50.000000 favimp=50.000000
Width Width_Z0=50R [InNetClass('Z0=50R')] p3 off: maxlimit=4.92 minlimit=4.68 preferedwidth=4.68 toplayer_minwidth=4.92 toplayer_prefwidth=4.92 bottomlayer_minwidth=4.92 bottomlayer_prefwidth=4.92 minimp=50.000000 maximp=50.000000 favimp=50.000000
Width [All and not InAnyDifferentialPair] p4: maxlimit=100 minlimit=4.68 preferedwidth=10 minimp=50.000000 maximp=50.000000 favimp=50.000000 checkconnectedcopper=TRUE
13 further rules are at their usual default settings.

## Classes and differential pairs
net class PHY1_CLK: RGMII1_RXCLK RGMII1_RXCLK_R RGMII1_TXCLK RGMII1_TXCLK_R
net class PWR: VAUX1 VAUX2 VAUX33 VDIG2 VMMC
component class TIDA-00204_revE3_Sitara_SC_0: C191 C192 C193 C194 C195 C196 C197 C198 C199 C200 C201 R69 R70 R71 R72 R73 R74 R75 R76 R77 R78 R79 R80 R81 R82 R83 R84 R85 R86 R87 R88 R89 R90 R91 R92 R93 R94 R95 R96 R97 R98 R99 R100 R101 R102 R103 R104 R105 R106 R107 R108 R109 R110 R111 R112 R113 R114 R115 R116 R117 R118 R119 R174 R175 R176 S1 U15 U16 Y3 Y4
component class TIDA-00204_Hardware: FID1 FID2 FID3 FID4 FID5 FID6 H1 H2 H3 H4 H5 H6 H7 H8 Logo2
component class "Mounting Holes": H1 H2 H3 H4
component class TIDA-00204_revE3_PS_0: C1 C2 C3 C4 C5 C6 C7 C8 C9 C10 C11 C12 C13 C14 D1 D2 J1 J2 L1 L2 R1 R2 R3 R4 R5 R6 R7 U1
component class TIDA-00204_revE3_PS_2: C80 C81 C82 C83 C84 C85 C86 C87 C88 C89 C90 C91 C92 C93 C94 C95 C96 C97 C98 C99 C100 C101 C260 D14 L3 L4 L5 R66 R67 U13 U14
component class TIDA-00204_revE3_Memory: C202 C203 C204 C205 C206 C207 C208 C209 C210 C211 C212 C213 C214 C215 C216 C217 C218 C219 C220 C221 C222 C223 C224 C225 C226 C227 C228 C229 C230 C231 C232 C233 J6 R120 R121 R122 R123 R124 R125 R126 R127 R128 R129 R130 R131 R132 R133 R134 R135 R136 R137 R138 TP1 TP2 U17 U18 U19 U20
component class TIDA-00204_revE3_PS_1: C15 C16 C17 C18 C21 C22 C23 C24 D3 J3 R8 R9 R10 R12 R13 R14 R15 R16 U2 U3 U5
component class TIDA-00204_revE3_Sitara_PS: C102 C103 C104 C105 C106 C107 C108 C109 C110 C111 C112 C113 C114 C115 C116 C117 C118 C119 C120 C121 C122 C123 C124 C125 C126 C127 C128 C129 C130 C131 C132 C133 C134 C135 C136 C137 C138 C139 C140 C141 C142 C143 C144 C145 C146 C147 C148 C149 C150 C151 C152 C153 C154 C155 C156 C157 C158 C159 C160 C161 C162 C163 C164 C165 C166 C167 C168 C169 C170 C171 C172 C173 C174 C175 C176 C177 C178 C179 C180 C181 C182 C183 C184 C185 C186 C187 C188 C189 C190 L6 L7 R68
component class TIDA-00204_revE3_PHY_1: C25 C26 C27 C28 C29 C30 C31 C32 C33 C34 C35 C36 C37 C38 C39 C40 C41 C42 C43 C44 C45 C46 C47 C48 C49 C50 C261 C262 C263 C264 C265 C266 C267 C268 D4 D5 D6 D7 J4 R19 R20 R21 R22 R23 R24 R25 R26 R27 R28 R29 R30 R31 R32 R33 R34 R35 R36 R37 R38 R170 R171 T1 U6 U7 U8 U9 U10 U11 Y1
component class Header: J1 J3
component class TIDA-00204_revE3_JTAGUSB: C234 C235 C236 C237 C238 C239 C240 C241 C242 C243 C244 C245 C246 C247 C248 C249 C250 C251 J7 J8 L8 L9 L10 L11 L12 R139 R140 R141 R142 R143 R144 R145 R146 R147 R148 R149 R150 R151 R152 R153 R154 R155 R156 R157 R158 R159 R160 R161 R162 R163 R164 R165 U21 U22 U23 U24 Y5
component class TIDA-00204_revE3_PHY_2: C53 C54 C55 C56 C57 C58 C59 C60 C61 C62 C63 C64 C65 C66 C67 C68 C69 C70 C71 C72 C73 C74 C75 C76 C77 C252 C253 C254 C255 C256 C257 C258 C259 C271 C272 C273 C274 C275 C276 C277 C278 D8 D9 D10 D11 D12 D13 J5 L13 L14 R41 R42 R43 R44 R45 R46 R47 R48 R49 R50 R51 R52 R53 R54 R55 R56 R57 R58 R59 R60 R61 R62 R63 R64 R65 R166 R167 R168 R169 R172 R173 R177 R178 R179 R180 R181 R182 R183 T2 TP3 TP4 U12 U25 Y2 Y6
component class FiducialMark: FID1 FID2 FID3 FID4 FID5 FID6
net class Zdiff=100R: DDR_CLK_N DDR_CLK_P DDR_DQS0_N DDR_DQS0_P DDR_DQS1_N DDR_DQS1_P PHY1_TD_A_N PHY1_TD_A_P PHY1_TD_B_N PHY1_TD_B_P PHY1_TD_C_N PHY1_TD_C_P PHY1_TD_D_N PHY1_TD_D_P PHY1_X_A_N PHY1_X_A_P PHY1_X_B_N PHY1_X_B_P PHY1_X_C_N PHY1_X_C_P PHY1_X_D_N PHY1_X_D_P PHY2_TD_A_N PHY2_TD_A_P PHY2_TD_B_N PHY2_TD_B_P PHY2_TD_C_N PHY2_TD_C_P PHY2_TD_D_N PHY2_TD_D_P PHY2_X_A_N PHY2_X_A_P PHY2_X_B_N PHY2_X_B_P PHY2_X_C_N PHY2_X_C_P PHY2_X_D_N PHY2_X_D_P
net class Z0=50R: DDR_A0 DDR_A1 DDR_A2 DDR_A3 DDR_A4 DDR_A5 DDR_A6 DDR_A7 DDR_A8 DDR_A9 DDR_A10 DDR_A11 DDR_A12 DDR_A13 DDR_BA0 DDR_BA1 DDR_BA2 DDR_CASN DDR_CKE DDR_CSN DDR_D0 DDR_D1 DDR_D2 DDR_D3 DDR_D4 DDR_D5 DDR_D6 DDR_D7 DDR_D8 DDR_D9 DDR_D10 DDR_D11 DDR_D12 DDR_D13 DDR_D14 DDR_D15 DDR_DQM0 DDR_DQM1 DDR_ODT DDR_RASN DDR_RESETN DDR_WEN RGMII1_RXCLK RGMII1_RXCLK_R RGMII1_RXCTRL RGMII1_RXCTRL_R RGMII1_RXD0 RGMII1_RXD0_R RGMII1_RXD1 RGMII1_RXD1_R RGMII1_RXD2 RGMII1_RXD2_R RGMII1_RXD3 RGMII1_RXD3_R RGMII1_TXCLK RGMII1_TXCLK_R RGMII1_TXCTRL RGMII1_TXCTRL_R RGMII1_TXD0 RGMII1_TXD0_R RGMII1_TXD1 RGMII1_TXD1_R RGMII1_TXD2 RGMII1_TXD2_R RGMII1_TXD3 RGMII1_TXD3_R RGMII2_RXCLK RGMII2_RXCLK_R RGMII2_RXCTRL RGMII2_RXCTRL_R RGMII2_RXD0 RGMII2_RXD0_R RGMII2_RXD1 RGMII2_RXD1_R RGMII2_RXD2 RGMII2_RXD2_R RGMII2_RXD3 RGMII2_RXD3_R RGMII2_TXCLK_R RGMII2_TXCTRL_R RGMII2_TXD0_R RGMII2_TXD1_R RGMII2_TXD2_R RGMII2_TXD3_R
net class Zdiff=90R: USBD_FT_N USBD_FT_P USBD_N USBD_P
component class "BGA 0.8mm": U8 U19
differential pair class Zdiff=100R: DDR_CLK DDR_DQS0 DDR_DQS1 PHY1_TD_A PHY1_TD_B PHY1_TD_C PHY1_TD_D PHY1_X_A PHY1_X_B PHY1_X_C PHY1_X_D PHY2_TD_A PHY2_TD_B PHY2_TD_C PHY2_TD_D PHY2_X_A PHY2_X_B PHY2_X_C PHY2_X_D
differential pair class Zdiff=90R: USBD USBD_FT
net class PHY1_X: PHY1_X_A_N PHY1_X_A_P PHY1_X_B_N PHY1_X_B_P PHY1_X_C_N PHY1_X_C_P PHY1_X_D_N PHY1_X_D_P
net class PHY1_TD: PHY1_TD_A_N PHY1_TD_A_P PHY1_TD_B_N PHY1_TD_B_P PHY1_TD_C_N PHY1_TD_C_P PHY1_TD_D_N PHY1_TD_D_P
net class PHY2_TD: PHY2_TD_A_N PHY2_TD_A_P PHY2_TD_B_N PHY2_TD_B_P PHY2_TD_C_N PHY2_TD_C_P PHY2_TD_D_N PHY2_TD_D_P
net class PHY2_X: PHY2_X_A_N PHY2_X_A_P PHY2_X_B_N PHY2_X_B_P PHY2_X_C_N PHY2_X_C_P PHY2_X_D_N PHY2_X_D_P
net class RGMII1_RX_R: RGMII1_RXCLK_R RGMII1_RXCTRL_R RGMII1_RXD0_R RGMII1_RXD1_R RGMII1_RXD2_R RGMII1_RXD3_R
net class RGMII1_TX_R: RGMII1_TXCLK_R RGMII1_TXCTRL_R RGMII1_TXD0_R RGMII1_TXD1_R RGMII1_TXD2_R RGMII1_TXD3_R
net class RGMII1_RX: RGMII1_RXCLK RGMII1_RXCTRL RGMII1_RXD0 RGMII1_RXD1 RGMII1_RXD2 RGMII1_RXD3
net class RGMII1_TX: RGMII1_TXCLK RGMII1_TXCTRL RGMII1_TXD0 RGMII1_TXD1 RGMII1_TXD2 RGMII1_TXD3
net class RGMII2_RX: RGMII2_RXCLK RGMII2_RXCTRL RGMII2_RXD0 RGMII2_RXD1 RGMII2_RXD2 RGMII2_RXD3
net class RGMII2_RX_R: RGMII2_RXCLK_R RGMII2_RXCTRL_R RGMII2_RXD0_R RGMII2_RXD1_R RGMII2_RXD2_R RGMII2_RXD3_R
net class RGMII2_TX: RGMII2_TXCLK RGMII2_TXCTRL RGMII2_TXD0 RGMII2_TXD1 RGMII2_TXD2 RGMII2_TXD3
net class RGMII2_TX_R: RGMII2_TXCLK_R RGMII2_TXCTRL_R RGMII2_TXD0_R RGMII2_TXD1_R RGMII2_TXD2_R RGMII2_TXD3_R
net class CLKs: DDR_CLK_N DDR_CLK_P MDIO_CLK_1 MDIO_CLK_2 MMC1_CLK PHY1_CLKOUT
net class PHY2_CLK: RGMII2_RXCLK RGMII2_RXCLK_R RGMII2_TXCLK RGMII2_TXCLK_R
differential pair DDR_DQS1: +DDR_DQS1_P -DDR_DQS1_N
differential pair DDR_DQS0: +DDR_DQS0_P -DDR_DQS0_N
differential pair DDR_CLK: +DDR_CLK_P -DDR_CLK_N
differential pair PHY2_X_D: +PHY2_X_D_P -PHY2_X_D_N
differential pair PHY2_X_C: +PHY2_X_C_P -PHY2_X_C_N
differential pair PHY2_X_B: +PHY2_X_B_P -PHY2_X_B_N
differential pair PHY2_X_A: +PHY2_X_A_P -PHY2_X_A_N
differential pair PHY2_TD_D: +PHY2_TD_D_P -PHY2_TD_D_N
differential pair PHY2_TD_C: +PHY2_TD_C_P -PHY2_TD_C_N
differential pair PHY2_TD_B: +PHY2_TD_B_P -PHY2_TD_B_N
differential pair PHY2_TD_A: +PHY2_TD_A_P -PHY2_TD_A_N
differential pair PHY1_X_D: +PHY1_X_D_P -PHY1_X_D_N
differential pair PHY1_X_C: +PHY1_X_C_P -PHY1_X_C_N
differential pair PHY1_X_B: +PHY1_X_B_P -PHY1_X_B_N
differential pair PHY1_X_A: +PHY1_X_A_P -PHY1_X_A_N
differential pair PHY1_TD_D: +PHY1_TD_D_P -PHY1_TD_D_N
differential pair PHY1_TD_C: +PHY1_TD_C_P -PHY1_TD_C_N
differential pair PHY1_TD_B: +PHY1_TD_B_P -PHY1_TD_B_N
differential pair PHY1_TD_A: +PHY1_TD_A_P -PHY1_TD_A_N
differential pair USBD_FT: +USBD_FT_P -USBD_FT_N
differential pair USBD: +USBD_P -USBD_N

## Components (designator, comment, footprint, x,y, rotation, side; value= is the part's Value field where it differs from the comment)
C1 "C1608X5R1E106M080AC" 0603 1775,3152.5 r180 top
C2 "C1608X5R1E106M080AC" 0603 1775,3092.5 r180 top
C3 "C1608X5R1E106M080AC" 0603 1775,3032.5 r180 top
C4 "GRM21BR72A474KA73L" 0805_HV 1310,3377.5 r180 top
C5 "C2012X7S2A105K125AB" 0805_145 520,3065 r270 top
C6 "GRM188R72A104KA35D" 0603 647.5,3065 r270 top
C7 "GRM188R72A102KA01D" 0603 585,3065 r270 top
C8 "GRM188R72A104KA35D" 0603 647.5,2925 r90 top
C9 "GRM188R72A102KA01D" 0603 585,2925 r90 top
C10 "GRM188R71E105KA12D" 0603 1130,3392.5 r180 top
C11 "C5750X7S2A106M" 2220 1355,2877.5 r0 top
C12 "GRM155R71H223KA12D" 0402 1105,2917.5 r180 top
C13 "GRM188R61C475KAAJ" 0603 1130,3452.5 r180 top
C14 "GRM1555C1E8R2CA01D" 0402 1055,3067.5 r0 top
C15 "GRM155R71C104KA88D" 0402 1742.5,2335 r180 top
C16 "GRM188R71A105KA61D" 0603 1838.5,2476.5 r90 top
C17 "C1608X5R1E106M080AC" 0603 2205,2426 r90 top
C18 "C1608X5R1E106M080AC" 0603 2235,2536 r180 top
C21 "GRM155R71H471KA01D" 0402 2420,2481 r90 top
C22 "GRM155R71C104KA88D" 0402 2725,2464 r180 top
C23 "GRM188R71A225KE15D" 0603 2645,2294 r180 top
C24 "GRM155R71A104KA01D" 0402 2630,2464 r0 top
C25 "GRM033R71C102KA01D" 0201 2640,1852.5 r270 top
C26 "GRM033R71C102KA01D" 0201 2640,1392.5 r90 top
C27 "GRM155R71C104KA88D" 0402 3034.96,1851.87 r180 bottom
C28 "GRM155R71C104KA88D" 0402 3034.96,1734.94 r180 bottom
C29 "GRM155R71C104KA88D" 0402 3034.96,1618.01 r180 bottom
C30 "GRM155R71C104KA88D" 0402 3034.96,1501.08 r180 bottom
C31 "GRM1555C1H270JA01D" 0402 2687.5,1987.5 r270 top
C32 "GRM1555C1H270JA01D" 0402 2687.5,2082.5 r90 top
C33 "202R18W102KV4E" 1206_190 3762.5,1357.5 r270 bottom
C34 "1812GC102KA1" 1812 3405,1677.5 r180 bottom
C35 "GRM033R71A103KA01D" 0201 1997.5,1847.5 r270 top
C36 "C1608X5R1E106M080AC" 0603 2765,1735 r90 bottom
C37 "GRM033R71A103KA01D" 0201 2725,1730 r90 bottom
C38 "GRM033R71C102KA01D" 0201 2765,1533.92 r0 top
C39 "GRM033R71C102KA01D" 0201 2765,1691.4 r0 top
C40 "C1608X5R1E106M080AC" 0603 2355,1960 r0 top
C41 "GRM033R71A103KA01D" 0201 2325,1912.5 r0 top
C42 "GRM033R71C102KA01D" 0201 2492.5,1852.5 r270 bottom
C43 "GRM033R71C102KA01D" 0201 2220,1602.5 r270 bottom
C44 "GRM033R71C102KA01D" 0201 2482.5,1380 r0 bottom
C45 "C1608X5R1E106M080AC" 0603 2357.5,1845 r0 bottom
C46 "GRM033R71A103KA01D" 0201 2327.5,1797.5 r0 bottom
C47 "GRM033R71C102KA01D" 0201 2765,1612.5 r0 top
C48 "GRM033R71C102KA01D" 0201 2412.5,1797.5 r0 bottom
C49 "GRM033R71C102KA01D" 0201 2267.5,1602.5 r90 bottom
C50 "GRM033R71C102KA01D" 0201 2482.5,1427.5 r180 bottom
C53 "GRM033R71C102KA01D" 0201 2640,755 r270 top
C54 "GRM033R71C102KA01D" 0201 2640,295 r90 top
C55 "GRM155R71C104KA88D" 0402 3034.96,759.37 r180 bottom
C56 "GRM155R71C104KA88D" 0402 3034.96,642.44 r180 bottom
C57 "GRM155R71C104KA88D" 0402 3034.96,525.51 r180 bottom
C58 "GRM155R71C104KA88D" 0402 3034.96,408.58 r180 bottom
C59 "202R18W102KV4E" 1206_190 3862.5,340 r270 bottom
C60 "GRM1555C1H270JA01D" 0402 2687.5,890 r270 top
C61 "GRM1555C1H270JA01D" 0402 2687.5,985 r90 top
C62 "1812GC102KA1" 1812 3405,585 r180 bottom
C63 "C1608X5R1E106M080AC" 0603 2765,637.5 r90 bottom
C64 "GRM033R71A103KA01D" 0201 2725,632.5 r90 bottom
C65 "GRM033R71C102KA01D" 0201 2765,593.9 r0 top
C66 "GRM033R71C102KA01D" 0201 2765,436.42 r0 top
C67 "C1608X5R1E106M080AC" 0603 2355,862.5 r0 top
C68 "GRM033R71A103KA01D" 0201 2325,815 r0 top
C69 "GRM033R71C102KA01D" 0201 2492.5,757.5 r270 bottom
C70 "GRM033R71C102KA01D" 0201 2220,505 r270 bottom
C71 "GRM033R71C102KA01D" 0201 2482.5,282.5 r0 bottom
C72 "C1608X5R1E106M080AC" 0603 2357.5,747.5 r0 bottom
C73 "GRM033R71A103KA01D" 0201 2327.5,700 r0 bottom
C74 "GRM033R71C102KA01D" 0201 2765,515 r0 top
C75 "GRM033R71C102KA01D" 0201 2412.5,700 r0 bottom
C76 "GRM033R71C102KA01D" 0201 2267.5,505 r90 bottom
C77 "GRM033R71C102KA01D" 0201 2482.5,330 r180 bottom
C80 "C1608X5R1E106M080AC" 0603 730,2470 r90 top
C81 "C1608X5R1E106M080AC" 0603 655,2470 r90 top
C82 "GRM188R61C475KAAJ" 0603 525,2295 r0 bottom
C83 "GRM188R61C475KAAJ" 0603 525,2360 r0 bottom
C84 "GRM188R61C475KAAJ" 0603 725,2065 r0 bottom
C85 "GRM188R61C475KAAJ" 0603 525,2215 r0 bottom
C86 "C1608X5R1E106M080AC" 0603 882.5,2110 r270 top
C87 "GRM188R61C475KAAJ" 0603 665,2215 r180 bottom
C88 "C1608X5R1E106M080AC" 0603 325,2575.67 r270 top
C89 "C1608X5R1E106M080AC" 0603 525,2157.5 r0 bottom
C90 "C1608X5R1E106M080AC" 0603 695,1950 r90 top
C91 "GRM188R71A225KE15D" 0603 695,2295 r180 bottom
C92 "GRM188R71A225KE15D" 0603 375,2230 r180 bottom
C93 "GRM188R71A225KE15D" 0603 375,2330 r180 bottom
C94 "GRM188R71A225KE15D" 0603 375,2335 r180 top
C95 "GRM188R71A225KE15D" 0603 525,2442.5 r180 bottom
C96 "GRM188R71A225KE15D" 0603 375,2410 r180 bottom
C97 "GRM188R71A225KE15D" 0603 790,2110 r270 top
C98 "GRM188R71A225KE15D" 0603 605,2065 r180 bottom
C99 "GRM155R71A104KA01D" 0402 632.5,2150 r0 bottom
C100 "GRM188R71A105KA61D" 0603 1210.47,1851.69 r180 bottom
C101 "GRM188R71A105KA61D" 0603 1210.47,1691.69 r180 bottom
C102 "GRM033R71A103KA01D" 0201 1340,937.5 r270 bottom
C103 "GRM033R71A103KA01D" 0201 1277.5,882.5 r90 bottom
C104 "C1608X5R1E106M080AC" 0603 1332.5,775 r270 bottom
C105 "GRM033R71A103KA01D" 0201 1492.5,977.5 r270 bottom
C106 "GRM033R71A103KA01D" 0201 1437.5,955 r90 bottom
C107 "C1608X5R1E106M080AC" 0603 1442.5,775 r90 bottom
C108 "GRM033R71A103KA01D" 0201 1530,930 r270 bottom
C109 "GRM033R71A103KA01D" 0201 1542.5,850 r0 bottom
C110 "C1608X5R1E106M080AC" 0603 1517.5,775 r270 bottom
C111 "GRM033R71A103KA01D" 0201 1617.5,1145 r90 bottom
C112 "GRM033R71A103KA01D" 0201 1655,1162.5 r90 bottom
C113 "C1608X5R1E106M080AC" 0603 1777.5,1205 r270 bottom
C114 "GRM033R71A103KA01D" 0201 1685,1107.5 r90 bottom
C115 "GRM033R71A103KA01D" 0201 1717.5,1107.5 r90 bottom
C116 "C1608X5R1E106M080AC" 0603 1777.5,1052.5 r270 bottom
C117 "GRM033R71A103KA01D" 0201 1277.5,937.99 r90 bottom
C118 "GRM033R71A103KA01D" 0201 1340,882.5 r270 bottom
C119 "GRM033R71A103KA01D" 0201 1180,805 r90 bottom
C120 "GRM033R71A103KA01D" 0201 1230,870 r0 bottom
C121 "GRM033R71A103KA01D" 0201 1670,1230 r180 bottom
C122 "GRM033R71A103KA01D" 0201 1572.5,1192.5 r0 bottom
C123 "GRM033R71A103KA01D" 0201 1605,1255 r0 bottom
C124 "GRM033R71A103KA01D" 0201 1532.5,1337.5 r270 bottom
C125 "GRM033R71A103KA01D" 0201 1560,1337.5 r270 bottom
C126 "C1608X5R1E106M080AC" 0603 1225,775 r90 bottom
C127 "GRM033R71A103KA01D" 0201 1410,1287.5 r0 bottom
C128 "GRM033R71A103KA01D" 0201 1655,1310 r90 bottom
C129 "GRM033R71A103KA01D" 0201 1575,1067.5 r0 bottom
C130 "GRM033R71A103KA01D" 0201 1405,927.5 r270 bottom
C131 "C1608X5R1E106M080AC" 0603 1705,1340 r90 bottom
C132 "GRM033R71A103KA01D" 0201 1462.5,1287.5 r180 bottom
C133 "GRM033R71A103KA01D" 0201 1670,1200 r0 bottom
C134 "GRM033R71A103KA01D" 0201 1695,940 r0 bottom
C135 "GRM033R71A103KA01D" 0201 1695,1005 r0 bottom
C136 "GRM033R71A103KA01D" 0201 1695,1035 r0 bottom
C137 "GRM033R71A103KA01D" 0201 1640,972.5 r0 bottom
C138 "GRM033R71A103KA01D" 0201 1435,1240 r270 bottom
C139 "CL03A105MP3NSNC" 0201 1420,1367.5 r90 bottom
C140 "CL03A105MP3NSNC" 0201 1475,1392.5 r90 bottom
C141 "CL03A105MP3NSNC" 0201 1447.5,1392.5 r90 bottom
C142 "GRM033R71A103KA01D" 0201 1315,1392.5 r90 bottom
C143 "GRM033R71A103KA01D" 0201 1467.5,902.5 r270 bottom
C144 "GRM033R71A103KA01D" 0201 1392.5,1367.5 r90 bottom
C145 "CL03A105MP3NSNC" 0201 1247.5,1392.5 r90 bottom
C146 "GRM033R71A103KA01D" 0201 1365,1392.5 r90 bottom
C147 "GRM033R71A103KA01D" 0201 1497.5,902.5 r270 bottom
C148 "C1608X5R1E106M080AC" 0603 987.5,880 r90 bottom
C149 "C1608X5R1E106M080AC" 0603 970,1430 r270 bottom
C150 "CL03A104KP3NNNC" 0201 1290,1075 r0 bottom
C151 "CL03A104KP3NNNC" 0201 1290,1130 r0 bottom
C152 "CL03A104KP3NNNC" 0201 1290,1050 r0 bottom
C153 "CL03A104KP3NNNC" 0201 1290,995 r0 bottom
C154 "CL03A104KP3NNNC" 0201 1290,1020 r0 bottom
C155 "CL03A104KP3NNNC" 0201 1290,1232.5 r0 bottom
C156 "CL03A104KP3NNNC" 0201 1302.5,1282.5 r45 bottom
C157 "CL03A104KP3NNNC" 0201 1290,1185 r0 bottom
C158 "CL03A104KP3NNNC" 0201 1220,1312.5 r135 bottom
C159 "CL03A104KP3NNNC" 0201 1290,1209 r0 bottom
C160 "CL03A104KP3NNNC" 0201 765,1287.5 r90 bottom
C161 "CL03A104KP3NNNC" 0201 875,882.5 r90 top
C162 "CL03A104KP3NNNC" 0201 925,1430 r270 bottom
C163 "CL03A104KP3NNNC" 0201 1055,892.5 r90 bottom
C164 "CL03A104KP3NNNC" 0201 725,915 r270 bottom
C165 "CL03A104KP3NNNC" 0201 765,1352.5 r90 bottom
C166 "CL03A104KP3NNNC" 0201 797.5,1260 r90 top
C167 "CL03A104KP3NNNC" 0201 935,882.5 r90 bottom
C168 "CL03A104KP3NNNC" 0201 925,1430 r270 top
C169 "CL03A104KP3NNNC" 0201 732.5,1262.5 r270 bottom
C170 "C1608X5R1E106M080AC" 0603 1670,775 r270 bottom
C171 "C1608X5R1E106M080AC" 0603 1210,1552.5 r180 bottom
C172 "GRM033R71A103KA01D" 0201 1492.5,1030 r270 bottom
C173 "GRM033R71A103KA01D" 0201 1587.5,1010 r0 bottom
C174 "GRM033R71A103KA01D" 0201 1535,1010 r180 bottom
C175 "GRM033R71A103KA01D" 0201 1372,1019.75 r90 bottom
C176 "GRM033R71A103KA01D" 0201 1435,1176 r270 bottom
C177 "GRM033R71A103KA01D" 0201 1512.5,1130 r180 bottom
C178 "GRM033R71A103KA01D" 0201 1625,802.5 r270 bottom
C179 "GRM033R71A103KA01D" 0201 1200,1507.5 r180 bottom
C180 "GRM033R71A103KA01D" 0201 1435,1020 r90 bottom
C181 "GRM033R71A103KA01D" 0201 1422.5,1130 r0 bottom
C182 "GRM033R71A103KA01D" 0201 1372,1240.25 r90 bottom
C183 "GRM033R71A103KA01D" 0201 1435,1084 r90 bottom
C184 "GRM033R71A103KA01D" 0201 1360,1130 r180 bottom
C185 "C1608X5R1E106M080AC" 0603 1567.5,1465 r0 bottom
C186 "GRM033R71A103KA01D" 0201 1475,1460 r270 bottom
C187 "GRM033R71A103KA01D" 0201 1167.5,1442.5 r180 bottom
C188 "GRM033R71A103KA01D" 0201 1492.5,1240 r90 bottom
C189 "GRM033R71A103KA01D" 0201 1537.5,1240 r90 bottom
C190 "GRM033R71A103KA01D" 0201 1570,1130 r0 bottom
C191 "GRM033R71A103KA01D" 0201 1655,1367.5 r90 bottom
C192 "GRM1555C1H270JA01D" 0402 1385,655 r0 top
C193 "GRM1555C1H270JA01D" 0402 1510,655 r180 top
C194 "GRM1555C1H180JA01D" 0402 1265,1595 r180 top
C195 "GRM033R71A103KA01D" 0201 1355,1517.5 r270 top
C196 "GRM033R71A103KA01D" 0201 1382.5,1517.5 r270 top
C197 "GRM033R71C102KA01D" 0201 1410,1517.5 r270 top
C198 "GRM1555C1H180JA01D" 0402 1147.5,1595 r0 top
C199 "GRM155R71A104KA01D" 0402 1055,1202.5 r90 bottom
C200 "GRM033R71A103KA01D" 0201 1395,1817.5 r180 top
C201 "GRM188R71A225KE15D" 0603 1615,1892.5 r90 top
C202 "C1608X5R1E106M080AC" 0603 632.28,302.5 r0 bottom
C203 "GRM155R71A104KA01D" 0402 540,345 r0 bottom
C204 "GRM155R71A104KA01D" 0402 755,1215 r180 bottom
C205 "GRM033R71A103KA01D" 0201 767.28,325 r0 top
C206 "GRM155R71C104KA88D" 0402 737.5,610 r270 top
C207 "GRM155R71A104KA01D" 0402 1737.5,1507.5 r180 top
C208 "CL03A104KP3NNNC" 0201 460,1230 r0 bottom
C209 "GRM155R71A104KA01D" 0402 360,1390 r0 bottom
C210 "GRM033R71C102KA01D" 0201 265,1692.5 r90 bottom
C211 "C1608X5R1E106M080AC" 0603 845,1462.5 r0 top
C212 "C1608X5R1E106M080AC" 0603 410,835 r180 bottom
C213 "CL03A104KP3NNNC" 0201 635,982.5 r180 bottom
C214 "CL03A104KP3NNNC" 0201 725,972.5 r90 bottom
C215 "CL03A104KP3NNNC" 0201 370,940 r270 bottom
C216 "CL03A104KP3NNNC" 0201 370,1302.5 r90 bottom
C217 "CL03A104KP3NNNC" 0201 370,1035 r90 bottom
C218 "CL03A104KP3NNNC" 0201 702.5,870 r0 bottom
C219 "CL03A104KP3NNNC" 0201 617.5,917.5 r180 bottom
C220 "CL03A104KP3NNNC" 0201 635,1107.5 r180 bottom
C221 "CL03A104KP3NNNC" 0201 710,1075 r90 bottom
C222 "CL03A104KP3NNNC" 0201 425,982.5 r0 bottom
C223 "CL03A104KP3NNNC" 0201 425,907.5 r180 bottom
C224 "CL03A104KP3NNNC" 0201 370,1097.5 r270 bottom
C225 "C1608X5R1E106M080AC" 0603 800,1615 r0 top
C226 "C1608X5R1E106M080AC" 0603 555,1690 r90 bottom
C227 "C1608X5R1E106M080AC" 0603 407.5,1610 r270 top
C228 "CL03A104KP3NNNC" 0201 465,1690 r90 top
C229 "CL03A104KP3NNNC" 0201 770,1555 r0 top
C230 "CL03A104KP3NNNC" 0201 465,1675 r90 bottom
C231 "C1608X5R1E106M080AC" 0603 815,912.5 r270 top
C232 "C1608X5R1E106M080AC" 0603 970,1430 r270 top
C233 "GRM188R61C475KAAJ" 0603 190,1487.5 r90 bottom
C234 "GRM188R61C475KAAJ" 0603 2875,3492.5 r0 top
C235 "GRM033R71A103KA01D" 0201 2792.5,3417.5 r0 bottom
C236 "GRM155R71A104KA01D" 0402 2687.5,3307.5 r180 top
C237 "GRM155R71A104KA01D" 0402 2517.5,3307.5 r0 top
C238 "GRM033R71A103KA01D" 0201 1330,2025 r0 bottom
C239 "GRM155R71A104KA01D" 0402 2917.5,3267.5 r180 bottom
C240 "GRM1555C1H270JA01D" 0402 2730,3137.5 r0 bottom
C241 "GRM1555C1H270JA01D" 0402 2637.5,3137.5 r180 bottom
C242 "GRM155R71A104KA01D" 0402 1550,1910 r90 bottom
C243 "GRM033R71A103KA01D" 0201 1897.5,2040 r0 top
C244 "GRM155R71A104KA01D" 0402 2432.5,3070 r90 bottom
C245 "GRM155R71A104KA01D" 0402 2430,2897.5 r270 bottom
C246 "GRM155R71A104KA01D" 0402 2605,2897.5 r270 bottom
C247 "GRM155R71A104KA01D" 0402 2817.5,3020 r270 bottom
C248 "GRM155R71A104KA01D" 0402 2507.5,2897.5 r270 bottom
C249 "GRM155R71A104KA01D" 0402 2532.5,3215 r270 bottom
C250 "GRM155R71A104KA01D" 0402 2817.5,3127.5 r90 bottom
C251 "GRM188R61C475KAAJ" 0603 2707.5,2885 r90 bottom
C252 "CL03A104KP3NNNC" 0201 3185,1050 r90 bottom
C253 "GRM033R71C102KA01D" 0201 3115,1050 r90 bottom
C254 "GRM033R71A103KA01D" 0201 3150,1050 r90 bottom
C255 "CL03A104KP3NNNC" 0201 3185,935 r90 bottom
C256 "GRM033R71A103KA01D" 0201 3150,935 r90 bottom
C257 "GRM033R71C102KA01D" 0201 3115,935 r90 bottom
C258 "GRM1555C1H270JA01D" 0402 3032.5,1122.5 r0 bottom
C259 "GRM1555C1H270JA01D" 0402 2837.5,1122.5 r180 bottom
C260 "GRM188R71A225KE15D" 0603 375,2227.5 r180 top
C261 "GRM0335C1H4R7CA01D" 0201 2670,1490 r180 bottom
C262 "GRM0335C1H4R7CA01D" 0201 2670,1517.5 r180 bottom
C263 "GRM0335C1H4R7CA01D" 0201 2670,1550 r180 bottom
C264 "GRM0335C1H4R7CA01D" 0201 2670,1577.5 r180 bottom
C265 "GRM0335C1H4R7CA01D" 0201 2670,1647.5 r180 bottom
C266 "GRM0335C1H4R7CA01D" 0201 2670,1675 r180 bottom
C267 "GRM0335C1H4R7CA01D" 0201 2670,1707.5 r180 bottom
C268 "GRM0335C1H4R7CA01D" 0201 2670,1735 r180 bottom
C271 "GRM0335C1H4R7CA01D" 0201 2670,392.5 r180 bottom
C272 "GRM0335C1H4R7CA01D" 0201 2670,420 r180 bottom
C273 "GRM0335C1H4R7CA01D" 0201 2670,452.5 r180 bottom
C274 "GRM0335C1H4R7CA01D" 0201 2670,480 r180 bottom
C275 "GRM0335C1H4R7CA01D" 0201 2670,550 r180 bottom
C276 "GRM0335C1H4R7CA01D" 0201 2670,577.5 r180 bottom
C277 "GRM0335C1H4R7CA01D" 0201 2670,610 r180 bottom
C278 "GRM0335C1H4R7CA01D" 0201 2670,637.5 r180 bottom
D1 "MBRA160T3G" SMA 600,3267.5 r180 top
D2 "LG L29K-G2J1-24-Z" "LG L29K_GREEN" 137.5,2875 r180 top
D3 "LG L29K-G2J1-24-Z" "LG L29K_GREEN" 137.5,2825 r180 top
D4 "LY L29K-J1K2-26-Z" "LY L29K_Yellow" 2550,1250 r90 top
D5 "LS L29K-G1J2-1-Z" "LS L29K_Red" 2602.5,1250 r90 top
D6 "LG L29K-G2J1-24-Z" "LG L29K_GREEN" 2655,1250 r90 top
D7 "LO L29K-J2L1-24-Z" "LO L29K_Orange" 2497.5,1250 r90 top
D8 "SRV05-4.TCT" SOT-23-6 2895,642.5 r0 bottom
D9 "LY L29K-J1K2-26-Z" "LY L29K_Yellow" 2550,152.5 r90 top
D10 "LS L29K-G1J2-1-Z" "LS L29K_Red" 2602.5,152.5 r90 top
D11 "LG L29K-G2J1-24-Z" "LG L29K_GREEN" 2655,152.5 r90 top
D12 "LO L29K-J2L1-24-Z" "LO L29K_Orange" 2497.5,152.5 r90 top
D13 "SRV05-4.TCT" SOT-23-6 2895,407.82 r0 bottom
D14 "LG L29K-G2J1-24-Z" "LG L29K_GREEN" 137.5,2775 r180 top
FID1 "Fiducial" Fiducial10-20 485,3597.5 r0 top
FID2 "Fiducial" Fiducial10-20 4110,3537.5 r0 top
FID3 "Fiducial" Fiducial10-20 4110,137.5 r0 top
FID4 "Fiducial" Fiducial10-20 222.5,172.5 r180 bottom
FID5 "Fiducial" Fiducial10-20 4077.5,137.5 r180 bottom
FID6 "Fiducial" Fiducial10-20 4110,3577.5 r180 bottom
H1 "NY PMS 440 0025 PH" "NY PMS 440 0025 PH" 200,3540 r0 top locked
H2 "NY PMS 440 0025 PH" "NY PMS 440 0025 PH" 4400,3540 r0 top locked
H3 "NY PMS 440 0025 PH" "NY PMS 440 0025 PH" 1000,200 r0 top locked
H4 "NY PMS 440 0025 PH" "NY PMS 440 0025 PH" 4100,1075 r0 top locked
H5 "1902C" Keystone_1902C 200,3540 r180 bottom locked
H6 "1902C" Keystone_1902C 4400,3540 r180 bottom locked
H7 "1902C" Keystone_1902C 1000,200 r180 bottom locked
H8 "1902C" Keystone_1902C 4100,1075 r180 bottom locked
J1 "PEC02SAAN" CONN_PEC02SAAN 1830,2862.5 r270 top
J2 "RAPC722X" CONN_RAPC722X -185,3145 r180 top
J3 "PEC02SAAN" CONN_PEC02SAAN 1935,2500 r90 top
J4 "43202-8916" Molex_43202-8916 4325,1607.5 r90 top
J5 "43202-8916" Molex_43202-8916 4325,542.5 r90 top
J6 "502774-0891" Molex_502774-0891 367.82,361.99 r270 top
J7 "10104111-0001LF" FCI_10104111-0001LF 2782.5,3682.91 r180 top
J8 "TFM-110-02-S-D-A-K-TR" Samtec_TFM-110-02-S-D-A-K 1462.5,2142.52 r0 top
L1 "LPS3010-102MRB" LPS3010 765,2995 r270 top
L2 "MSS1260-153MLB" MSS1260 1635,3452.5 r0 top
L3 "VLCF5020T-2R2N2R6-3" VLCF5020 855,2300 r270 top
L4 "VLCF5020T-2R2N2R6-3" VLCF5020 495,2555 r180 top
L5 "VLCF5020T-2R2N2R6-3" VLCF5020 540,1995 r0 top
L6 "LI0805H151R-10" 0805_HV 1385,1647.5 r90 top
L7 "LI0805H151R-10" 0805_HV 1465,1647.5 r90 top
L8 "ACM2012H-900-2P-T00" TDK_ACM2012H-900-2P-T00 2702.58,3492.91 r0 top
L9 "LI0805H151R-10" 0805_HV 2712.5,3372.5 r180 top
L10 "LI0805H151R-10" 0805_HV 3045,3645 r90 top
L11 "LI0805H151R-10" 0805_HV 2492.5,3372.5 r0 top
L12 "LI0805H151R-10" 0805_HV 2895,2827.5 r90 top
L13 "MMZ1005Y121C" 0402 3230,1067.5 r270 bottom
L14 "MMZ1005Y121C" 0402 3230,952.5 r270 bottom
Logo2 "Pb-Free Symbol" Pb-Free_Overlay_Small 3612.5,3397.5 r0 top
R1 "CRCW060310R0JNEAHP" 0603 882.5,2995 r270 top
R2 "CRCW0402453KFKED" 0402 1105,2817.5 r0 top
R3 "CRCW0402750RJNED" 0402 245,2875 r0 top
R4 "CRCW0402100KFKED" 0402 1105,2867.5 r0 top
R5 "CRCW040280K6FKED" 0402 1120,3337.5 r0 top
R6 "CRCW04021M00FKED" 0402 1055,3022.5 r180 top
R7 "CRCW0402249KFKED" 0402 1105,2967.5 r180 top
R8 "CRCW06030000Z0EA" 0603 1875,2339 r180 top
R9 "CRCW06030000Z0EA" 0603 2645,2614 r0 top
R10 "CRCW06030000Z0EA" 0603 2170,2297.5 r0 top
R12 "CRCW06030000Z0EA" 0603 2305,2296 r0 top
R13 "CRCW0402360RJNED" 0402 245,2825 r0 top
R14 "CRCW0402150KFKED" 0402 2420,2376 r270 top
R15 "CRCW06030000Z0EA" 0603 2645,2534 r180 top
R16 "CRCW0402110KFKED" 0402 2465,2481 r270 top
R19 "CRCW04020000Z0ED" 0402 2340,1307.5 r0 top
R20 "EXB-2HVR000V" RESCAXS_EXB-2HV 2135,1522.82 r270 top
R21 "CRCW040210K0FKED" 0402 2747.5,1783.96 r270 top
R22 "CRCW060375R0FKEA" 0603 3730.04,1851.87 r0 bottom
R23 "CRCW04024K70JNED" 0402 2450,1960 r270 top
R24 "CRCW060375R0FKEA" 0603 3730.04,1734.94 r0 bottom
R25 "CRCW0402560RJNED" 0402 2550,1250 r90 bottom
R26 "CRCW0402560RJNED" 0402 2602.5,1250 r90 bottom
R27 "CRCW0402560RJNED" 0402 2655,1250 r90 bottom
R28 "CRCW040211K0FKED" 0402 2377.5,1250 r90 bottom
R29 "CRCW04024K70JNED" 0402 2562.5,1395 r270 bottom
R30 "CRCW040211K0FKED" 0402 2422.5,1250 r270 bottom
R31 "CRCW04022K49FKED" 0402 2332.5,1250 r90 bottom
R32 "CRCW060375R0FKEA" 0603 3730.04,1618.01 r0 bottom
R33 "CRCW0402560RJNED" 0402 2497.5,1250 r270 bottom
R34 "CRCW04022K49FKED" 0402 2422.5,1350 r270 bottom
R35 "CRCW040222R0JNED" 0402 2500,1960 r90 top
R36 "CRCW04021M00FKED" 0402 2640,2035 r90 top
R37 "CRCW060375R0FKEA" 0603 3730.04,1501.08 r0 bottom
R38 "CRCW040210K0FKED" 0402 1902.5,1920 r0 top
R41 "CRCW040210K0FKED" 0402 2750,687.5 r270 top
R42 "CRCW060375R0FKEA" 0603 3730.04,759.37 r0 bottom
R43 "CRCW04020000Z0ED" 0402 2340,207.5 r0 top
R44 "CRCW04020000Z0ED" 0402 2075,527.5 r270 top
R45 "CRCW04024K70JNED" 0402 2457.5,840 r270 top
R46 "CRCW04020000Z0ED" 0402 2101.97,459.47 r0 top
R47 "CRCW04020000Z0ED" 0402 2101.97,416.97 r0 top
R48 "CRCW060375R0FKEA" 0603 3730.04,642.44 r0 bottom
R49 "CRCW040211K0FKED" 0402 2250,285 r0 bottom
R50 "CRCW04020000Z0ED" 0402 2101.97,374.47 r0 top
R51 "CRCW04020000Z0ED" 0402 2101.97,331.97 r0 top
R52 "CRCW0402560RJNED" 0402 2550,152.5 r90 bottom
R53 "CRCW0402560RJNED" 0402 2602.5,152.5 r90 bottom
R54 "CRCW0402560RJNED" 0402 2655,152.5 r90 bottom
R55 "CRCW04024K70JNED" 0402 2562.5,297.5 r270 bottom
R56 "CRCW040211K0FKED" 0402 2377.5,152.5 r90 bottom
R57 "CRCW04022K49FKED" 0402 2250,327.5 r0 bottom
R58 "CRCW060375R0FKEA" 0603 3730.04,525.51 r0 bottom
R59 "CRCW040211K0FKED" 0402 2422.5,152.5 r270 bottom
R60 "CRCW0402560RJNED" 0402 2497.5,152.5 r270 bottom
R61 "CRCW04022K49FKED" 0402 2332.5,152.5 r90 bottom
R62 "CRCW04022K49FKED" 0402 2422.5,252.5 r270 bottom
R63 "CRCW04020000Z0ED" 0402 2512.5,937.5 r270 top
R64 "CRCW060375R0FKEA" 0603 3730.04,408.58 r0 bottom
R65 "CRCW04021M00FKED" 0402 2640,937.5 r90 top
R66 "CRCW0402560RJNED" 0402 245,2775 r0 top
R67 "CRCW040210K0FKED" 0402 680,2360 r180 bottom
R68 "CRCW040210K0FKED" 0402 1147.5,1507.5 r0 top
R69 "EXB-2HV220JV" RESCAXS_EXB-2HV 1827.5,1155 r270 top
R70 "CRCW040210K0JNED" 0402 1572.5,1572.5 r0 top
R71 "CRCW06030000Z0EA" 0603 1550,1662.5 r90 top
R72 "CRCW040222R0JNED" 0402 1875,1045 r0 bottom
R73 "CRCW040222R0JNED" 0402 1875,1035 r0 top
R74 "CRCW040222R0JNED" 0402 1875,987.5 r0 top
R75 "CRCW040222R0JNED" 0402 1875,997.5 r0 bottom
R76 "CRCW04022K20JNED" 0402 1875,955 r0 bottom
R77 "CRCW040222R0JNED" 0402 1827.16,927.5 r0 top
R78 "CRCW040222R0JNED" 0402 1681.22,687.73 r0 top
R79 "CRCW040222R0JNED" 0402 1827.16,842.5 r0 top
R80 "CRCW040222R0JNED" 0402 1827.16,885 r0 top
R81 "CRCW040222R0JNED" 0402 1681.22,730.23 r0 top
R82 "CRCW040222R0JNED" 0402 1681.22,772.73 r0 top
R83 "CRCW040210K0JNED" 0402 1677.5,385 r0 bottom
R84 "CRCW040210K0JNED" 0402 1347.5,385 r180 bottom
R85 "CRCW040210K0JNED" 0402 1677.5,342.5 r0 bottom
R86 "CRCW040210K0JNED" 0402 1347.5,342.5 r180 bottom
R87 "CRCW040210K0JNED" 0402 1677.5,300 r0 bottom
R88 "CRCW040210K0JNED" 0402 1347.5,300 r180 bottom
R89 "CRCW040210K0JNED" 0402 1677.5,257.5 r0 bottom
R90 "CRCW040210K0JNED" 0402 1347.5,257.5 r180 bottom
R91 "CRCW040210K0JNED" 0402 1677.5,215 r0 bottom
R92 "CRCW040210K0JNED" 0402 1347.5,215 r180 bottom
R93 "CRCW040210K0JNED" 0402 1677.5,172.5 r0 bottom
R94 "CRCW040210K0JNED" 0402 1347.5,172.5 r180 bottom
R95 "CRCW040210K0JNED" 0402 1677.5,130 r0 bottom
R96 "CRCW040210K0JNED" 0402 1347.5,130 r180 bottom
R97 "CRCW040210K0JNED" 0402 1677.5,87.5 r0 bottom
R98 "CRCW040210K0JNED" 0402 1347.5,87.5 r180 bottom
R99 "CRCW040249R9FKED" 0402 1120,1202.5 r270 bottom
R100 "CRCW04021K00FKED" 0402 1590,1810 r180 top
R101 "CRCW0402100KJNED" 0402 1567.5,385 r0 bottom
R102 "CRCW0402100KJNED" 0402 1457.5,385 r180 bottom
R103 "CRCW0402100KJNED" 0402 1567.5,342.5 r0 bottom
R104 "CRCW0402100KJNED" 0402 1457.5,342.5 r180 bottom
R105 "CRCW0402100KJNED" 0402 1567.5,300 r0 bottom
R106 "CRCW0402100KJNED" 0402 1457.5,300 r180 bottom
R107 "CRCW0402100KJNED" 0402 1567.5,257.5 r0 bottom
R108 "CRCW0402100KJNED" 0402 1457.5,257.5 r180 bottom
R109 "CRCW0402100KJNED" 0402 1567.5,215 r0 bottom
R110 "CRCW0402100KJNED" 0402 1457.5,215 r180 bottom
R111 "CRCW0402100KJNED" 0402 1567.5,172.5 r0 bottom
R112 "CRCW0402100KJNED" 0402 1457.5,172.5 r180 bottom
R113 "CRCW0402100KJNED" 0402 1567.5,130 r0 bottom
R114 "CRCW0402100KJNED" 0402 1457.5,130 r180 bottom
R115 "CRCW0402100KJNED" 0402 1567.5,87.5 r0 bottom
R116 "CRCW0402100KJNED" 0402 1457.5,87.5 r180 bottom
R117 "CRCW04022K20JNED" 0402 1625,1655 r180 top
R118 "CRCW04022K20JNED" 0402 1625,1702.5 r180 top
R119 "CRCW0402100KFKED" 0402 1385,1892.5 r270 top
R120 "CRCW040210K0JNED" 0402 540,480 r180 bottom
R121 "CRCW040210K0JNED" 0402 540,435 r180 bottom
R122 "CRCW040210K0JNED" 0402 540,390 r180 bottom
R123 "CRCW040210K0JNED" 0402 540,260 r180 bottom
R124 "CRCW040210K0JNED" 0402 540,215 r180 bottom
R125 "CRCW040210K0JNED" 0402 540,170 r180 bottom
R126 "CRCW040249R9FKED" 0402 755,1125 r0 bottom
R127 "CRCW040249R9FKED" 0402 755,1170 r0 bottom
R128 "EXB-2HV470JV" RESCAXS_EXB-2HV 465,1480 r180 bottom
R129 "CRCW04021K00FKED" 0402 807.5,1357.5 r270 top
R130 "EXB-2HV470JV" RESCAXS_EXB-2HV 535,1590 r0 top
R131 "CRCW040210K0JNED" 0402 335,1097.5 r90 bottom
R132 "CRCW0402240RJNED" 0402 335,1200 r270 bottom
R133 "EXB-2HV470JV" RESCAXS_EXB-2HV 645,1480 r180 bottom
R134 "CRCW040247R0JNED" 0402 820,1152.5 r90 bottom
R135 "CRCW040210K0JNED" 0402 247.5,1390 r180 bottom
R136 "CRCW040210K0FKED" 0402 250,1645 r0 bottom
R137 "CRCW040210K0JNED" 0402 247.5,1342.5 r180 bottom
R138 "CRCW040210K0FKED" 0402 225,1710 r270 bottom
R139 "CRCW06030000Z0EA" 0603 2205,3267.5 r180 top
R140 "CRCW06030000Z0EA" 0603 2205,3210 r180 top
